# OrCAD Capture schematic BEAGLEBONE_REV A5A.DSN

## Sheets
1 P01_Title Page: title: BeagleBone Cover Page; rev: A5; note: 450-5500-001
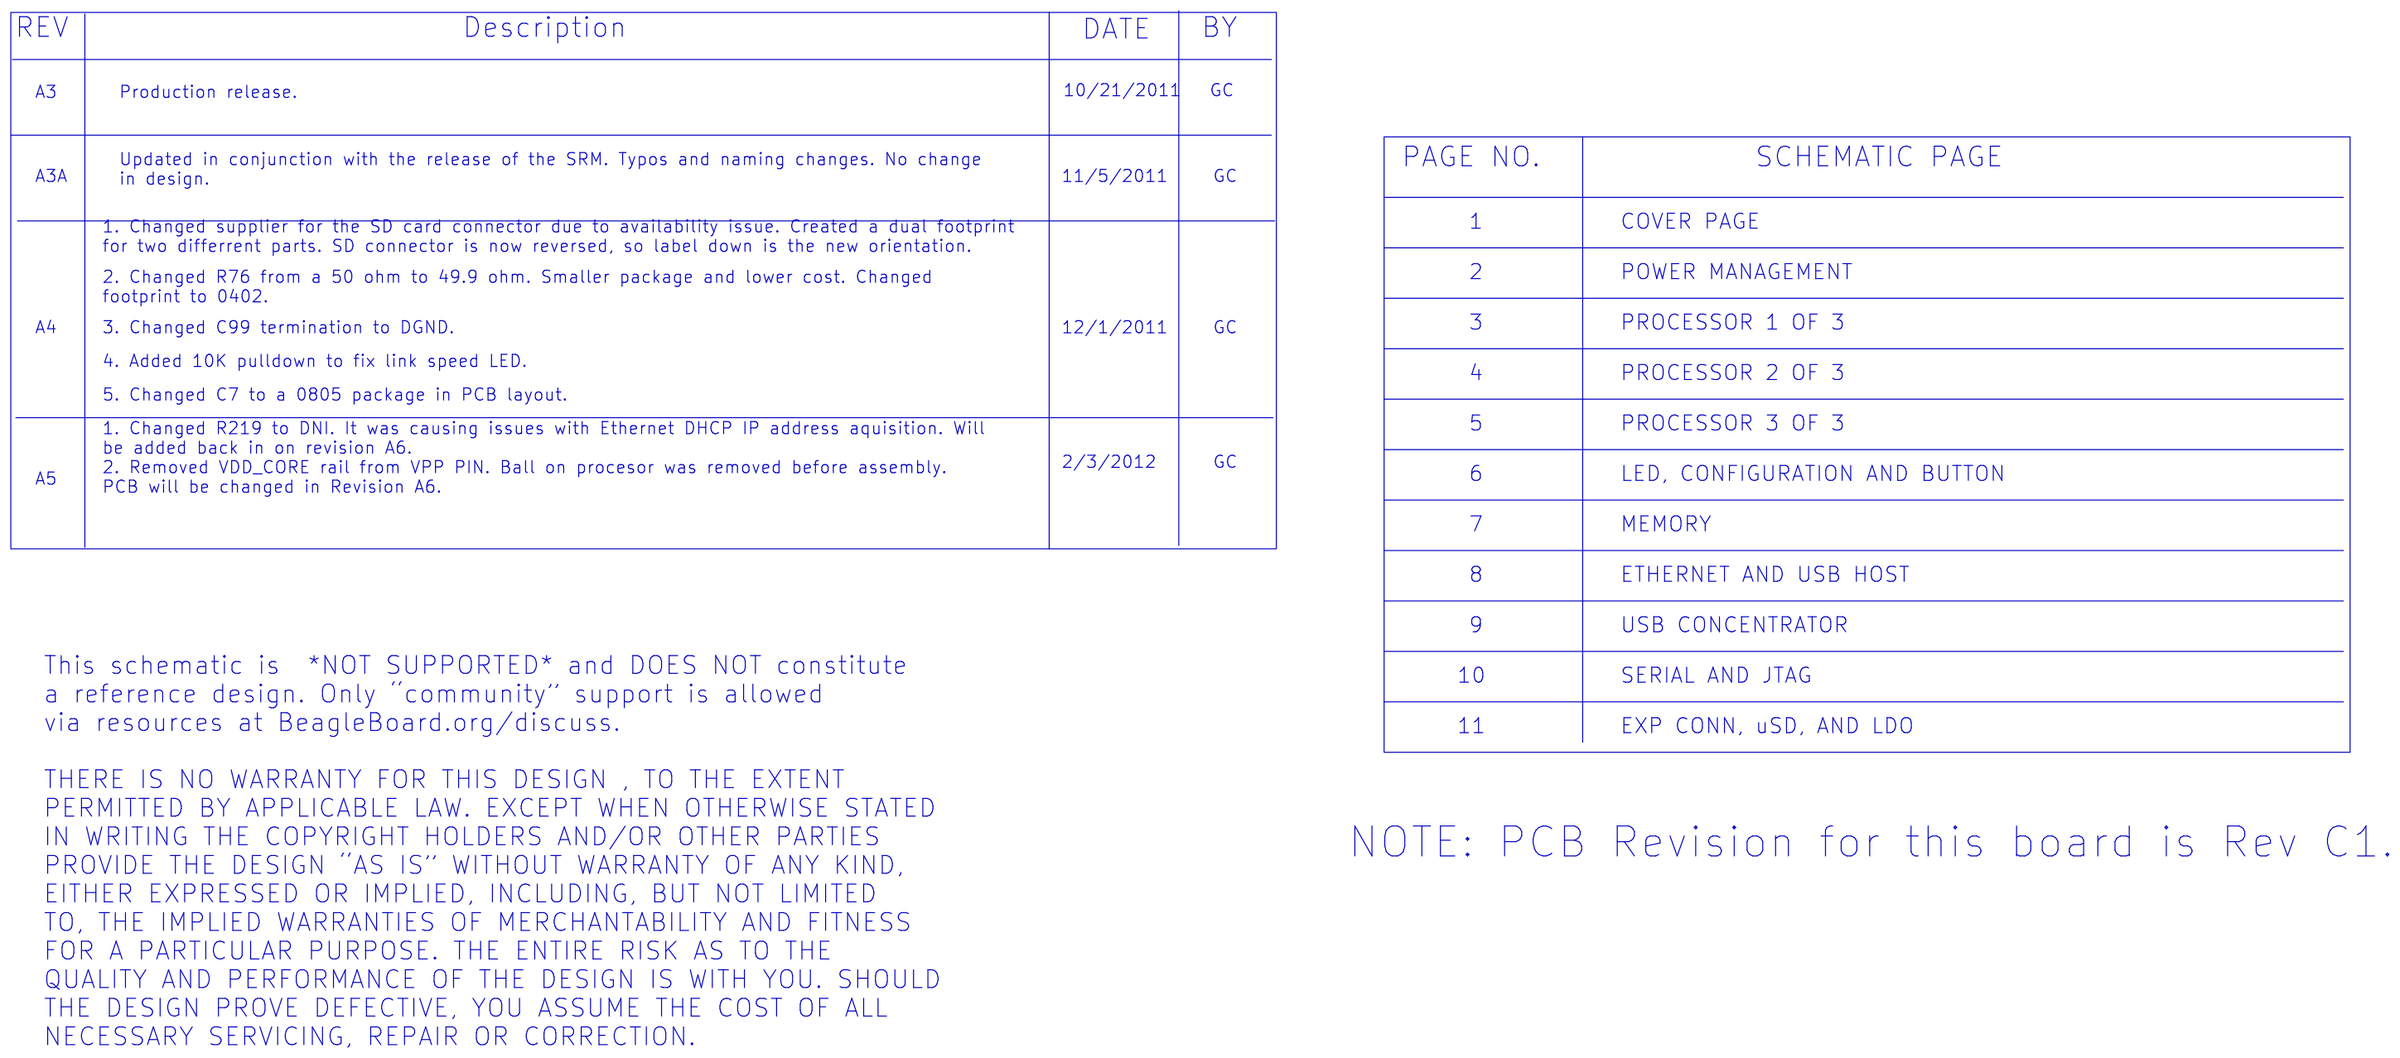
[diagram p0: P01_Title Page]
2 P02_Power Management: size B; title: BeagleBone Power Management
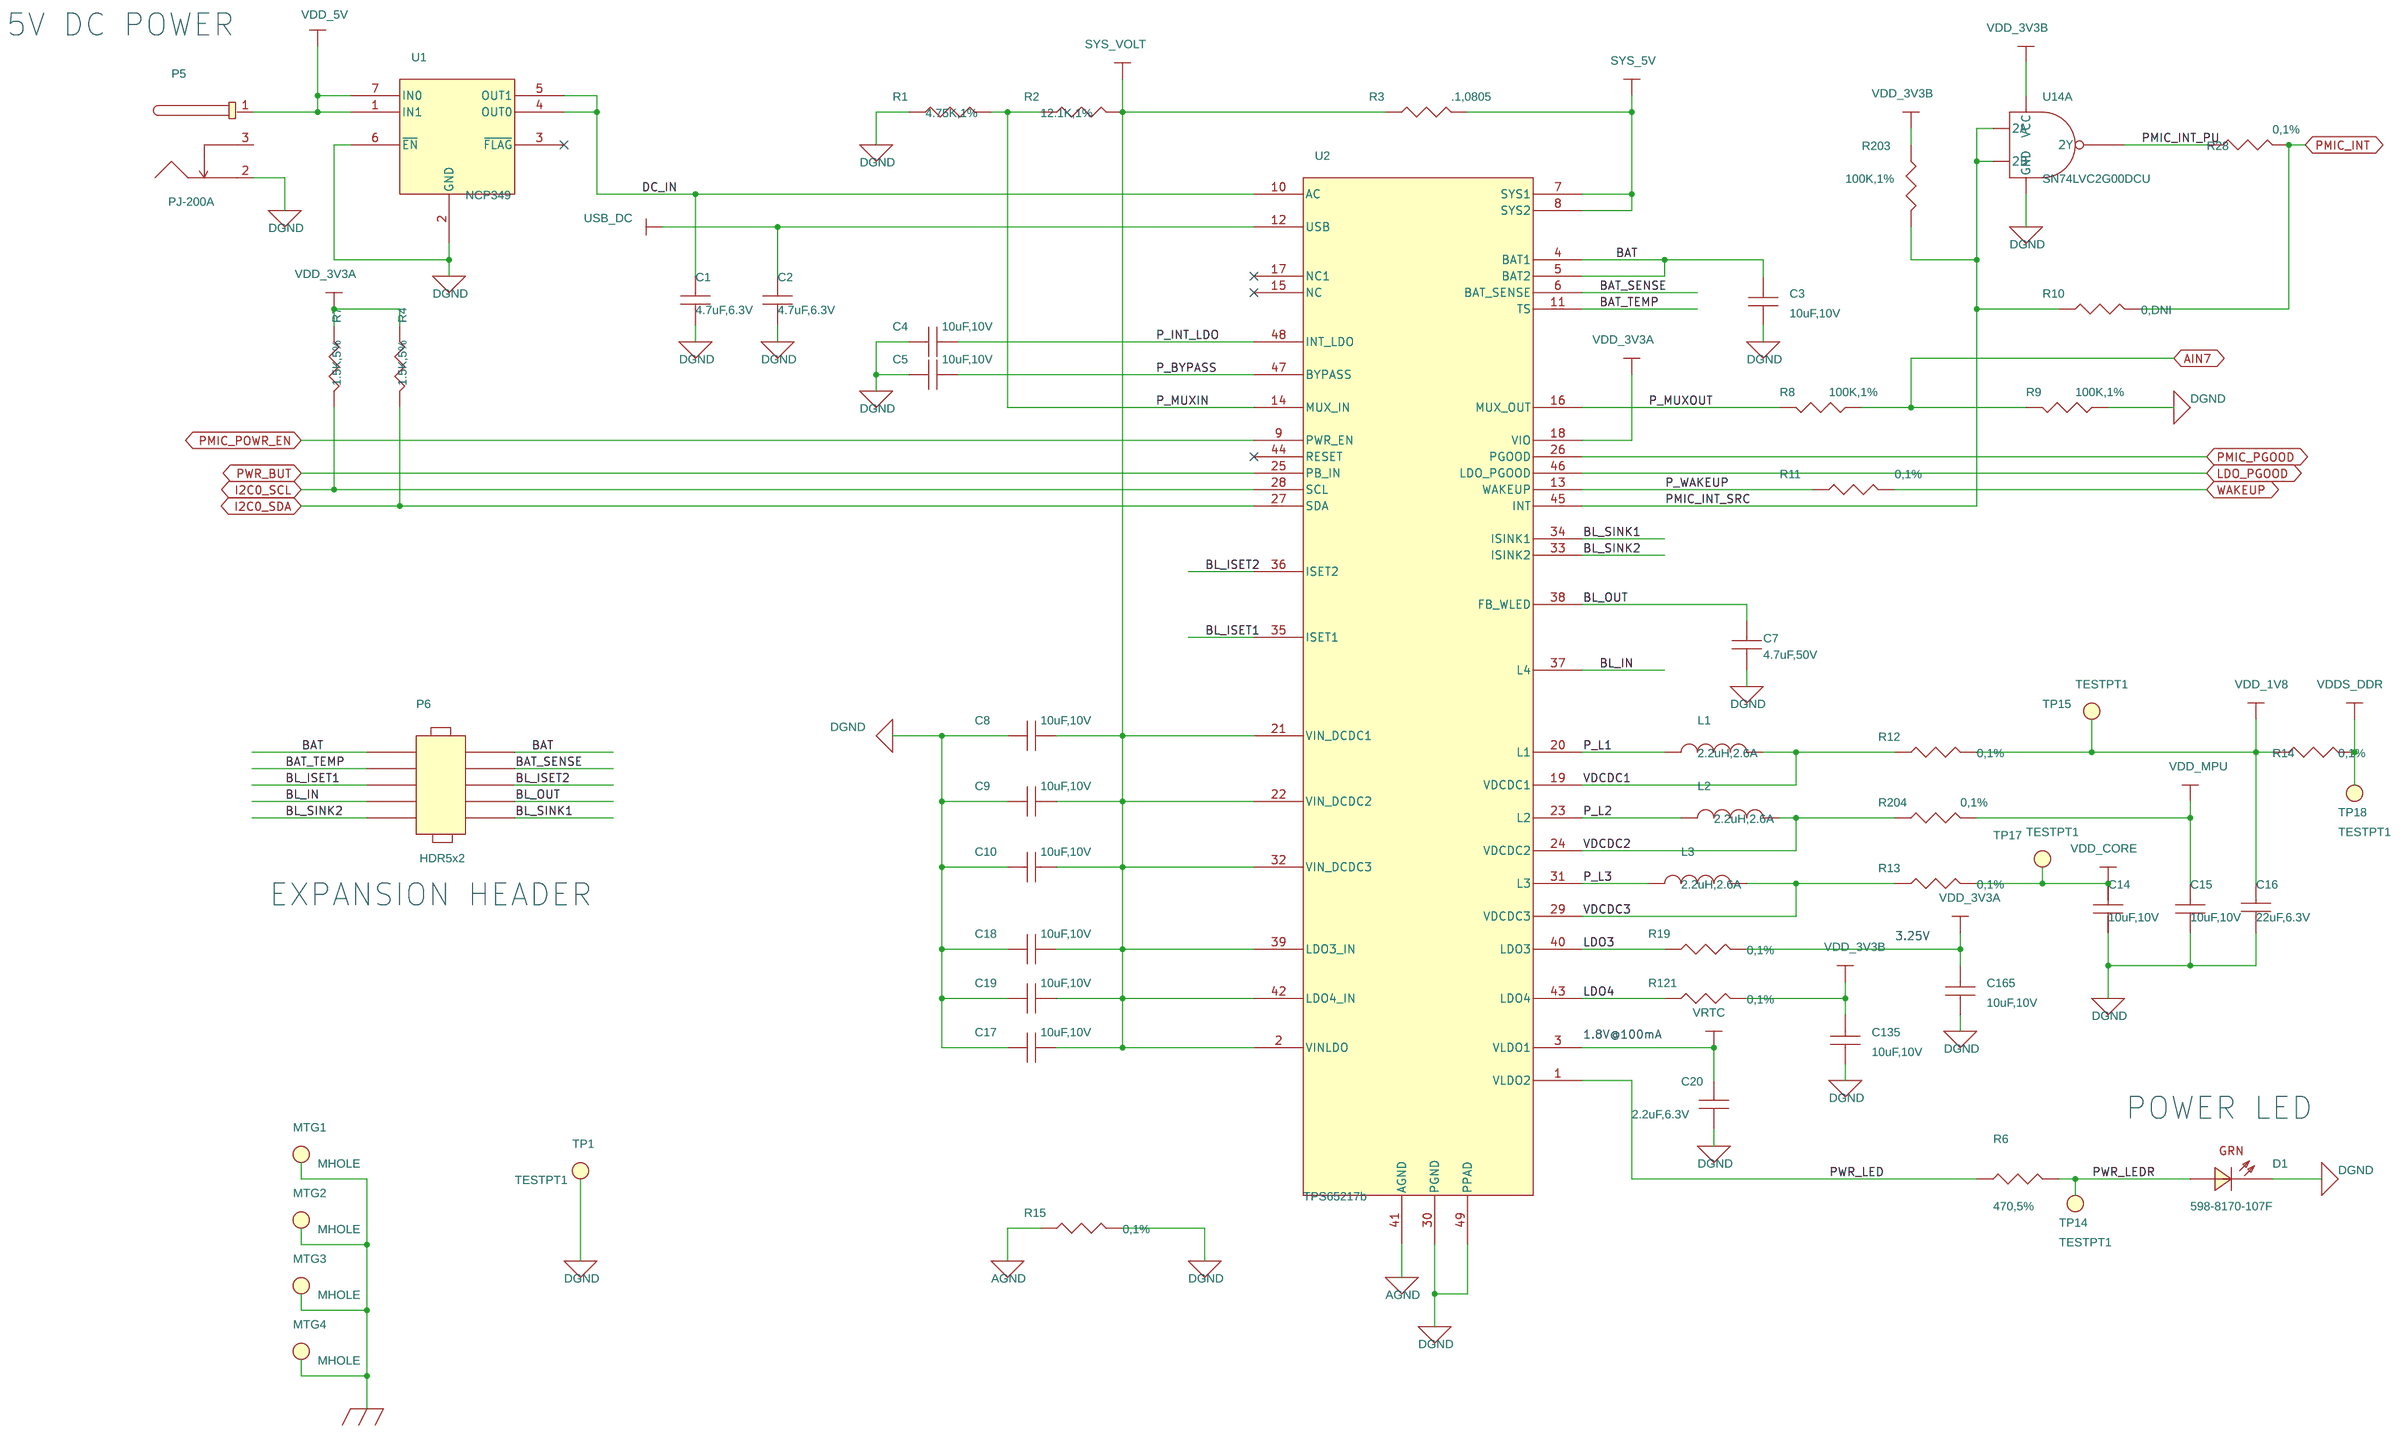
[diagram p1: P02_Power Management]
3 P03_AM335x Sheet 1 of 3: size C; title: BeagleBone Processor 1 of 3
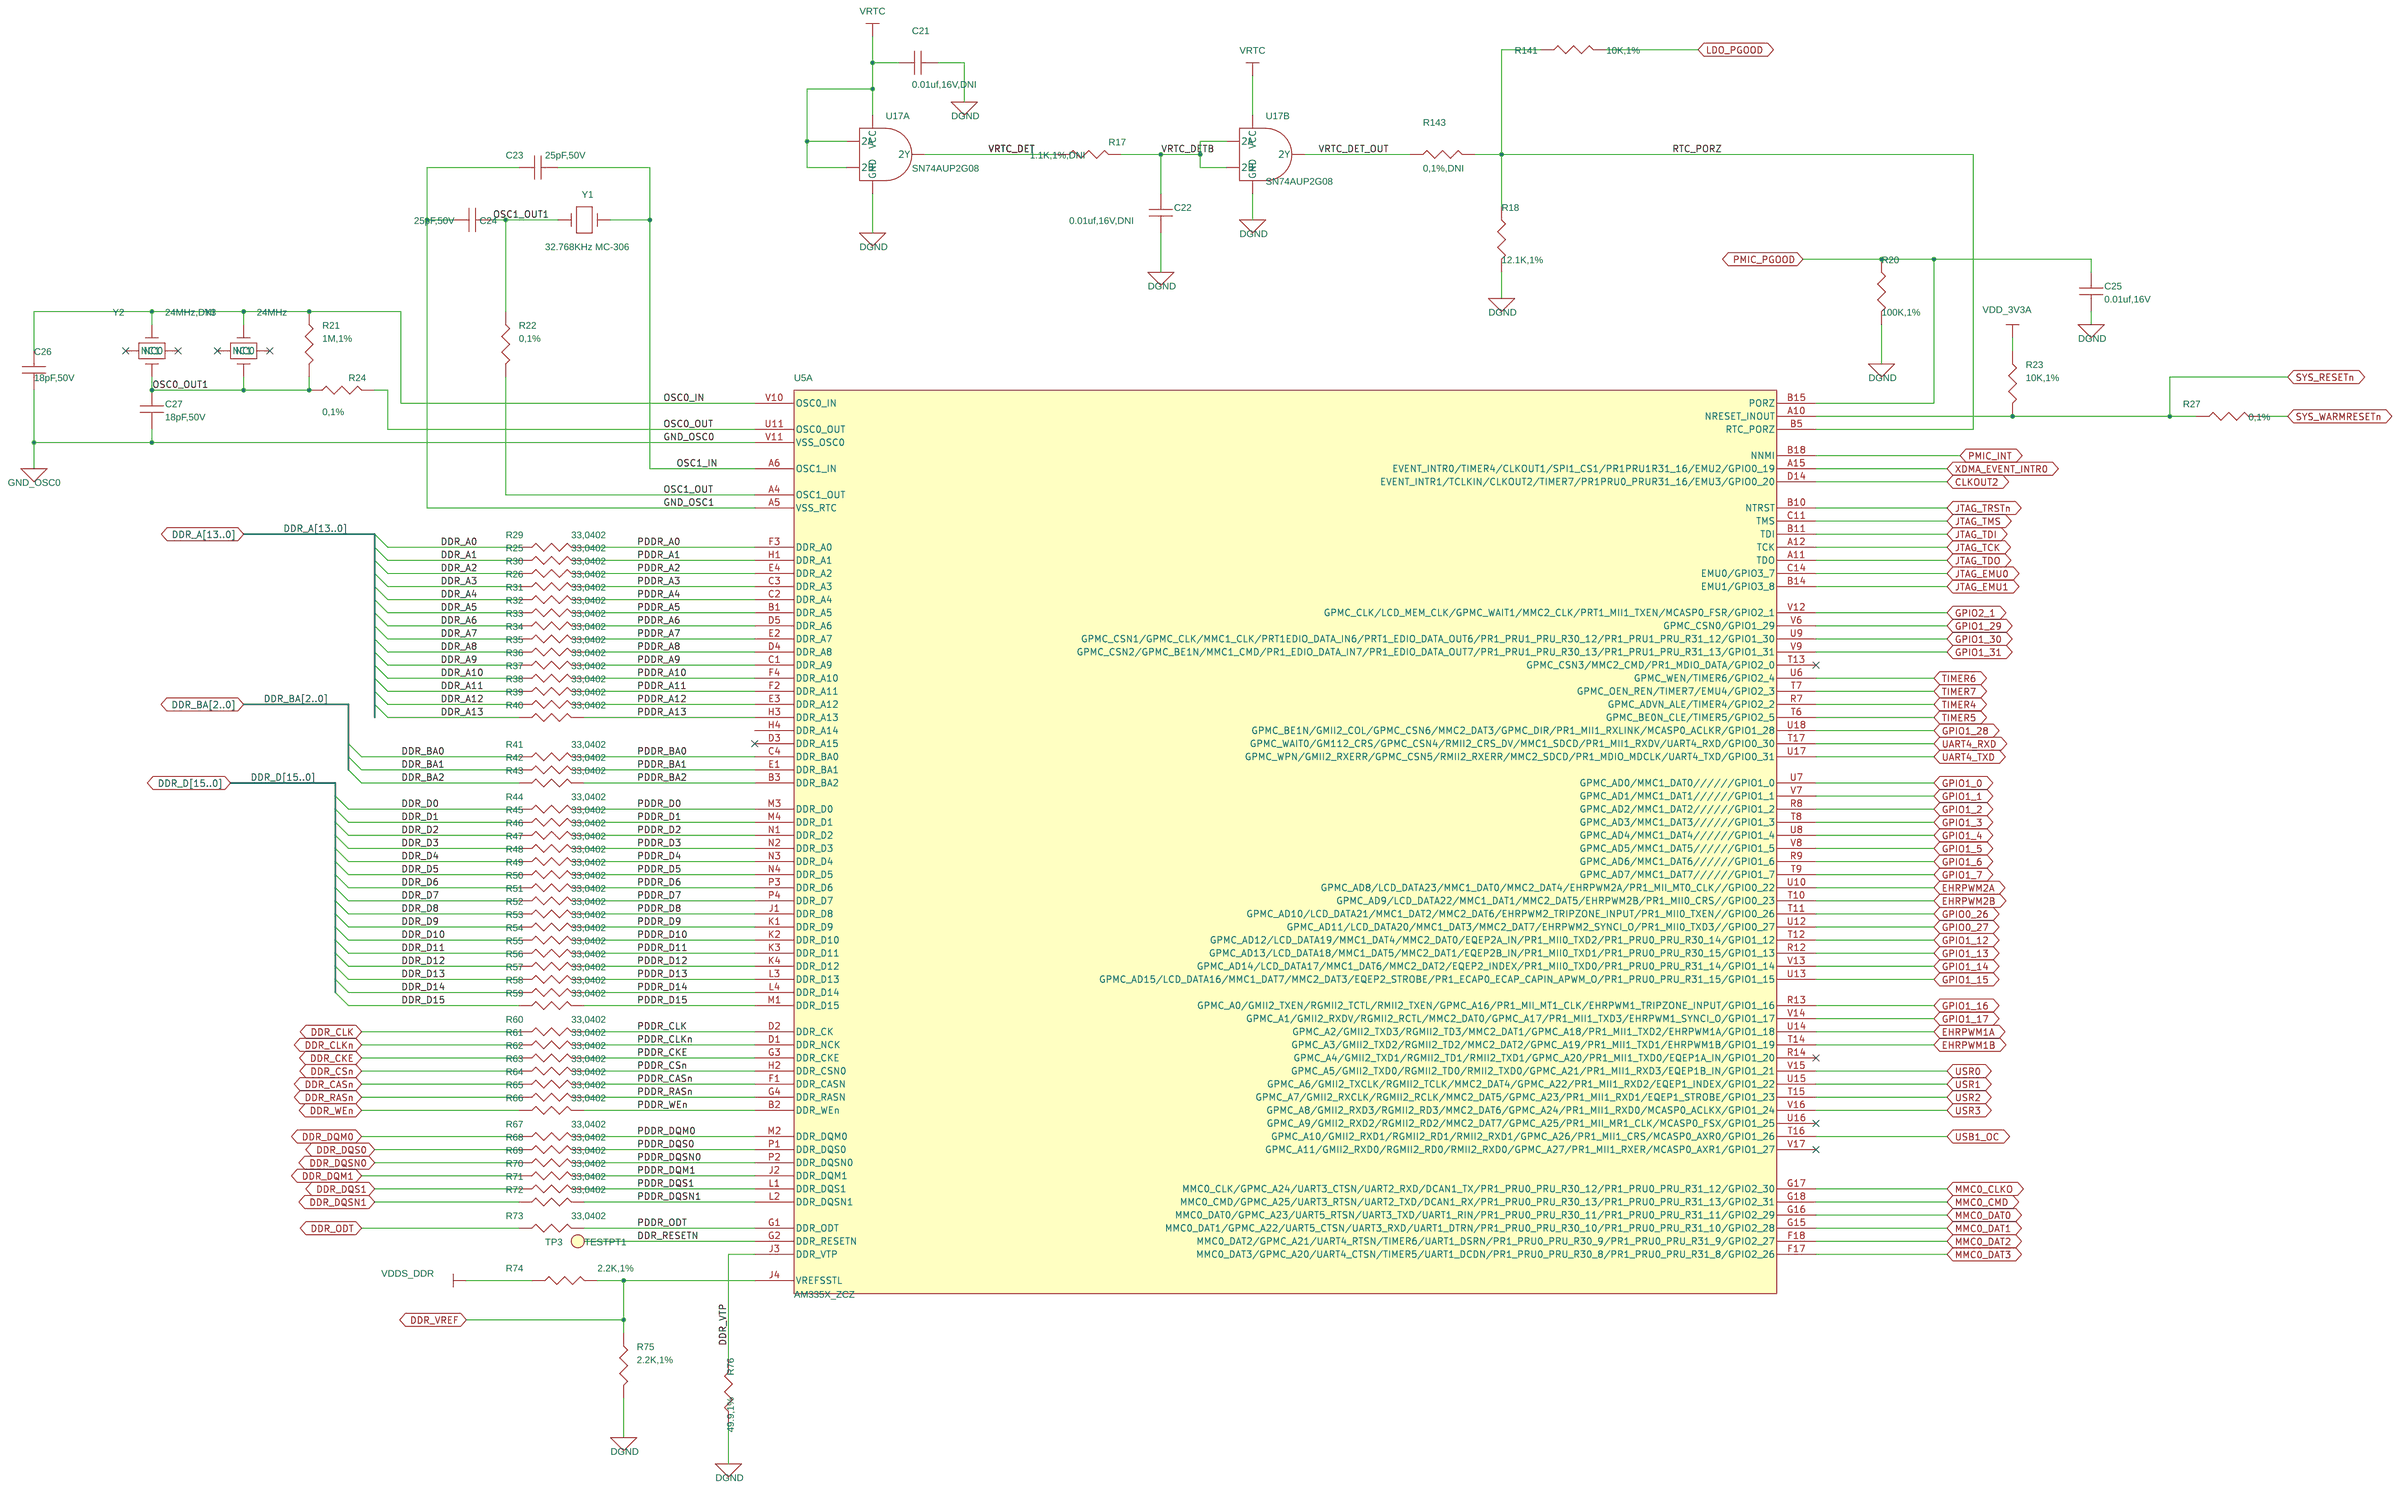
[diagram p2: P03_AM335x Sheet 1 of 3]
4 P04_AM335x Sheet 2 of 3: size C; title: BeagleBone Processor 2 of 3
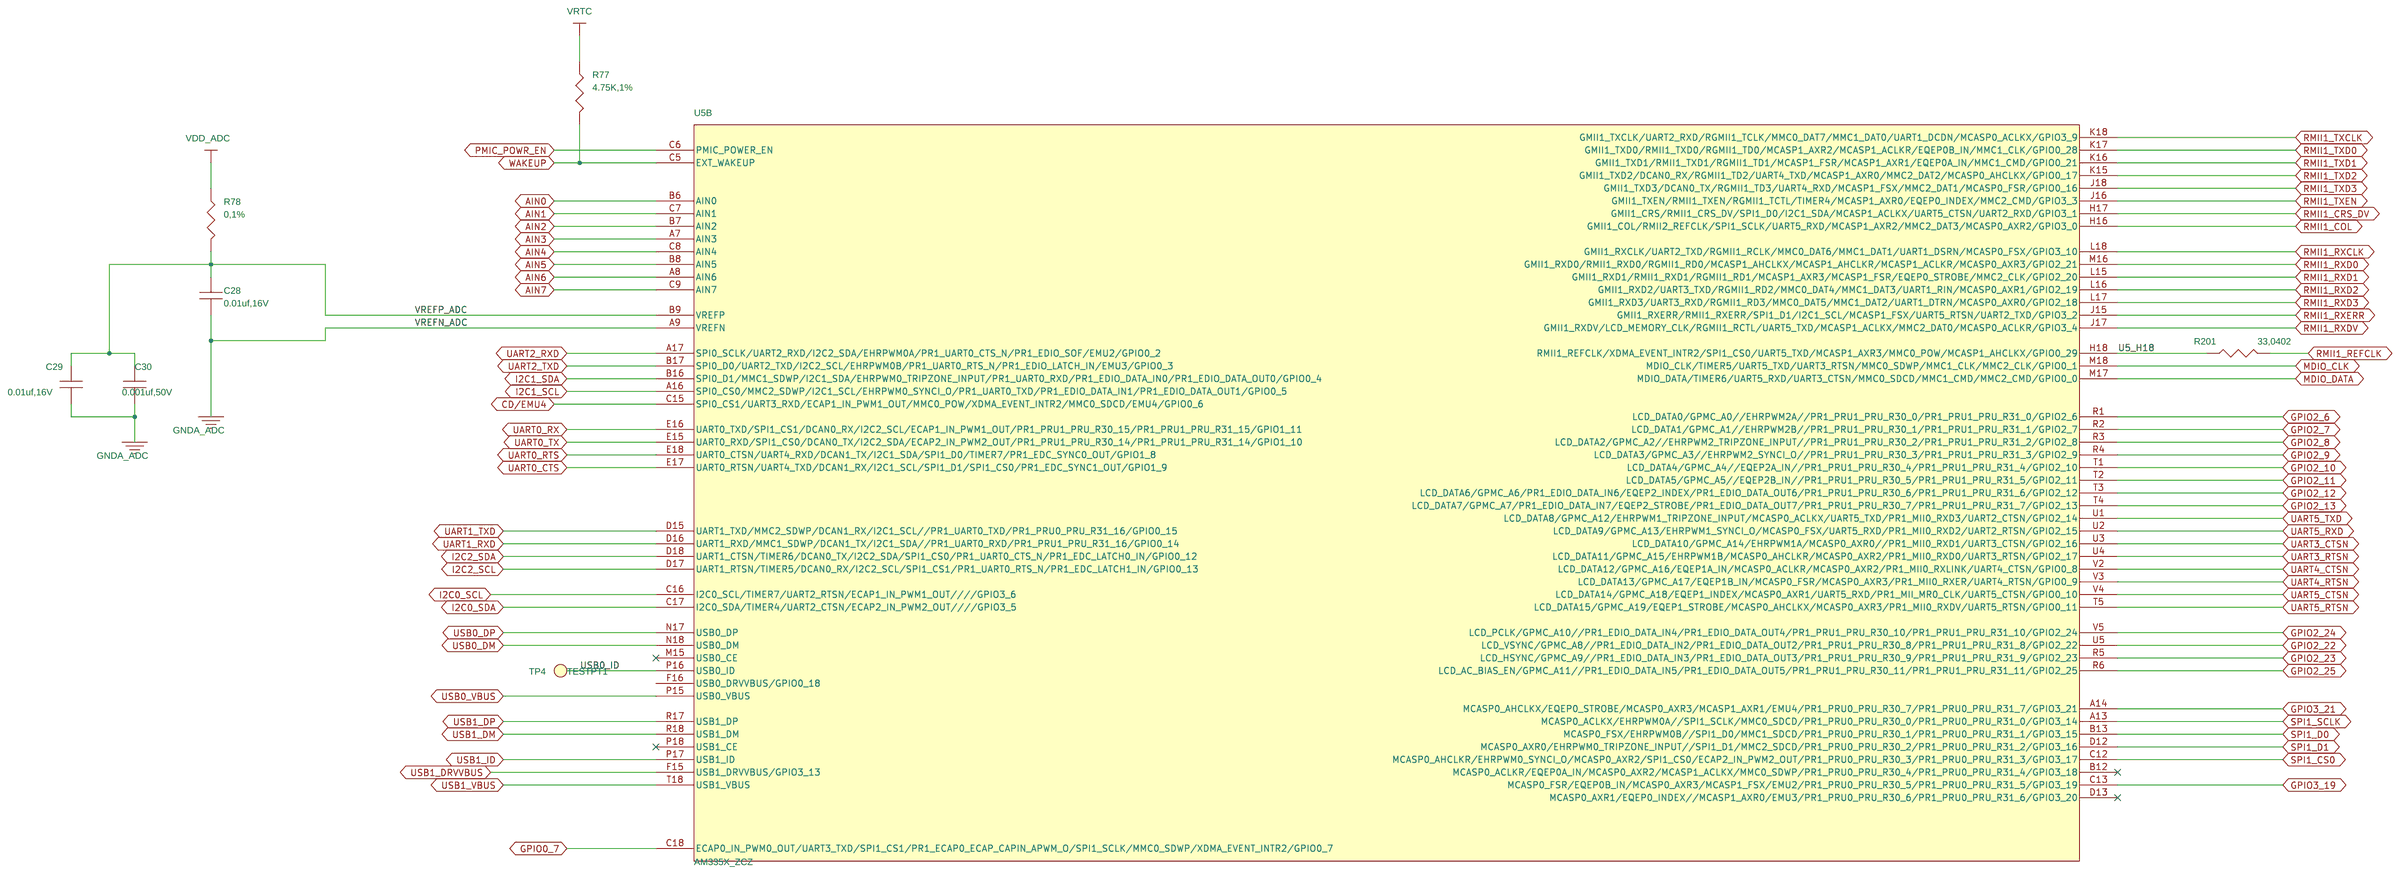
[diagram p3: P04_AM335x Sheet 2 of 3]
5 P05_AM335x Page 3 of 3: size C; title: BeagleBone Processr 3 of 3
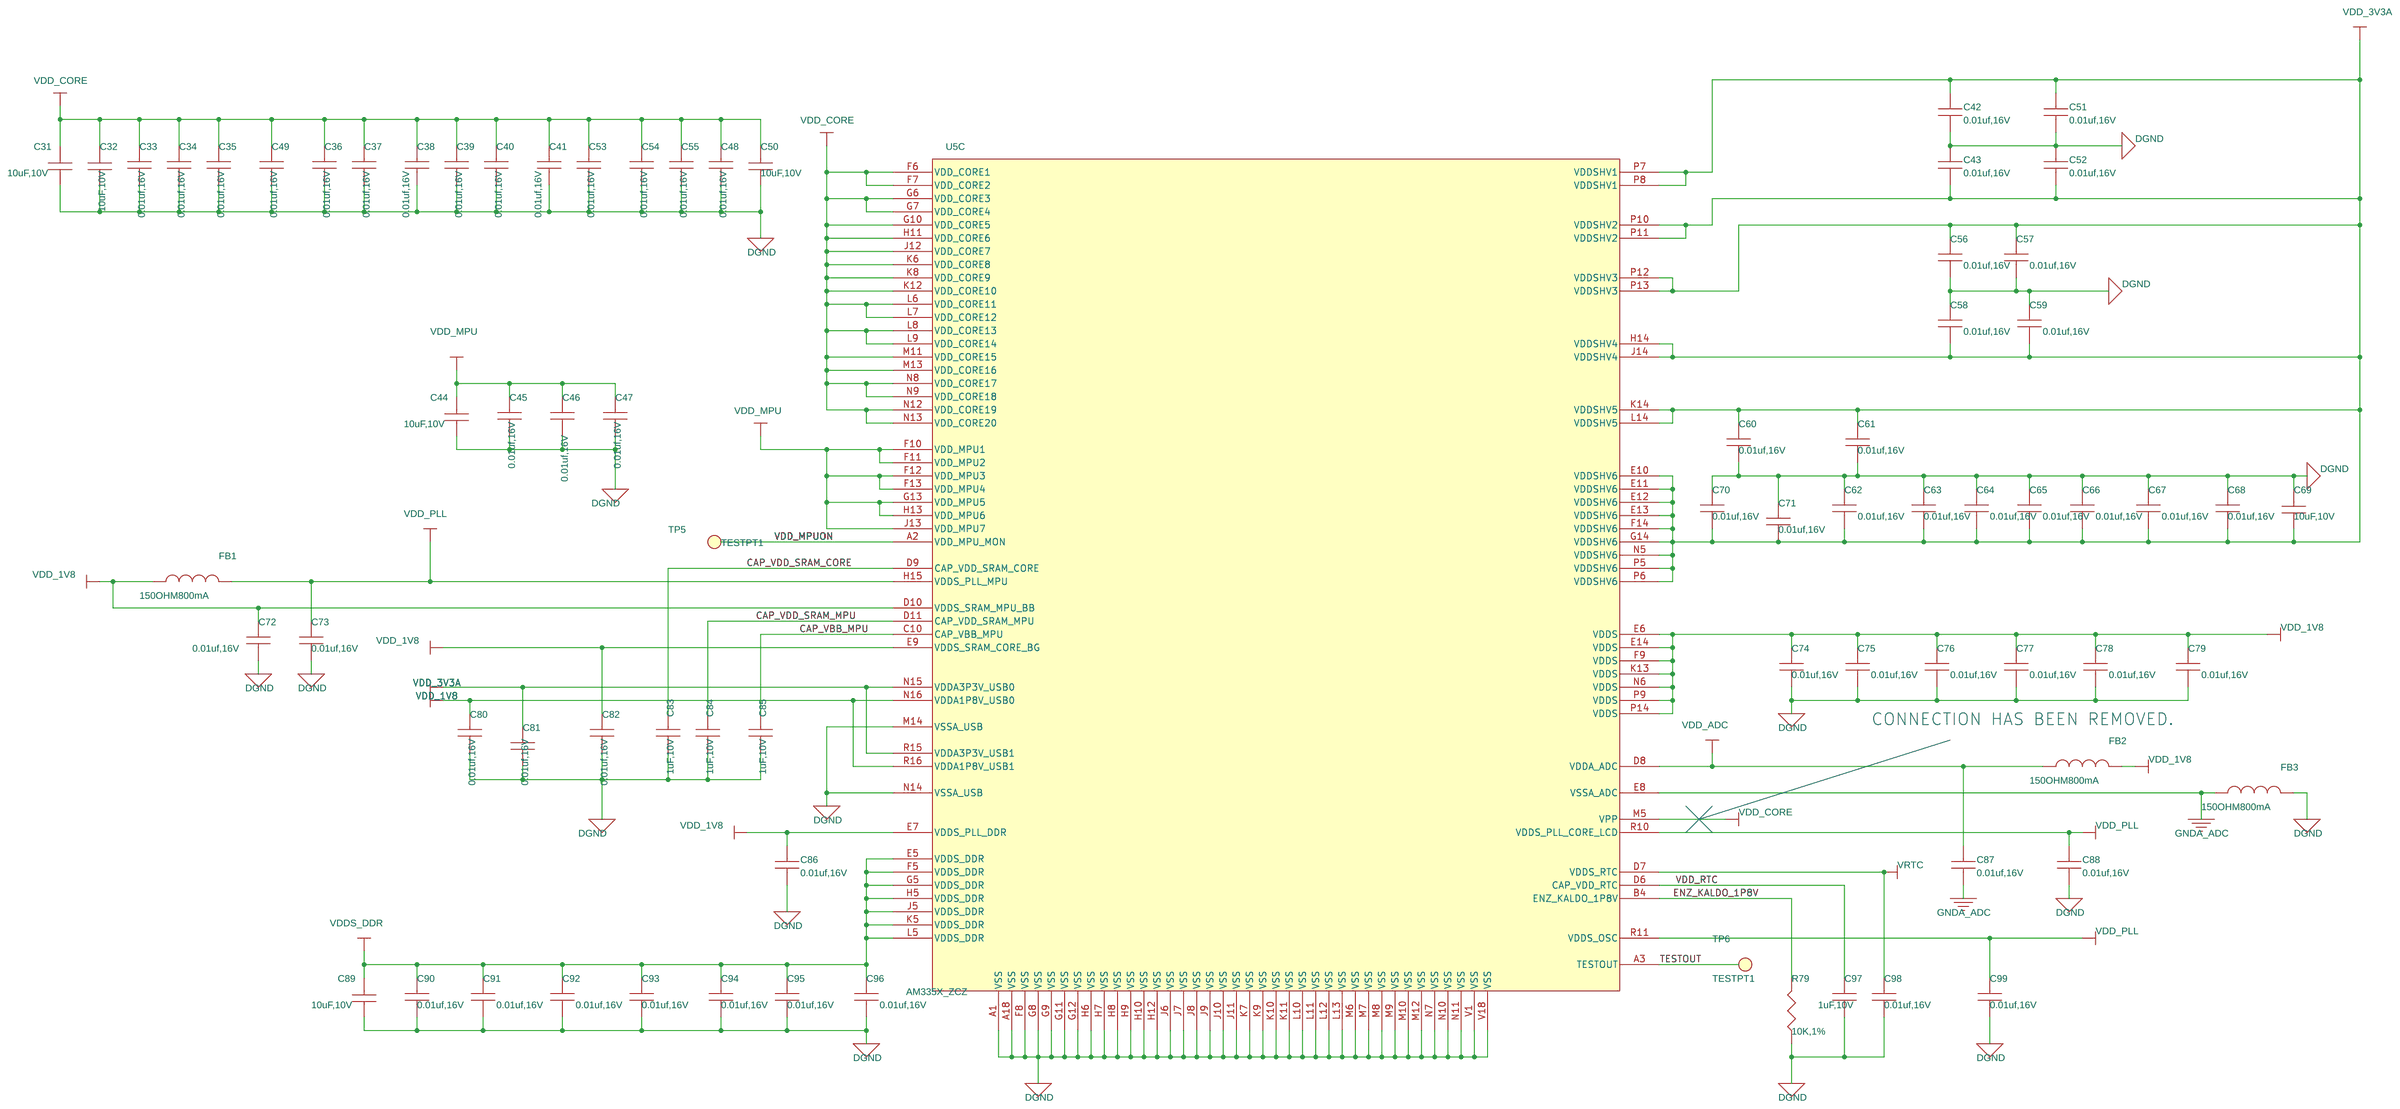
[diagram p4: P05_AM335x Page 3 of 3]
6 P06_LED, Config, & Reset: size B; title: BeagleBone LED, Configuration and Reset
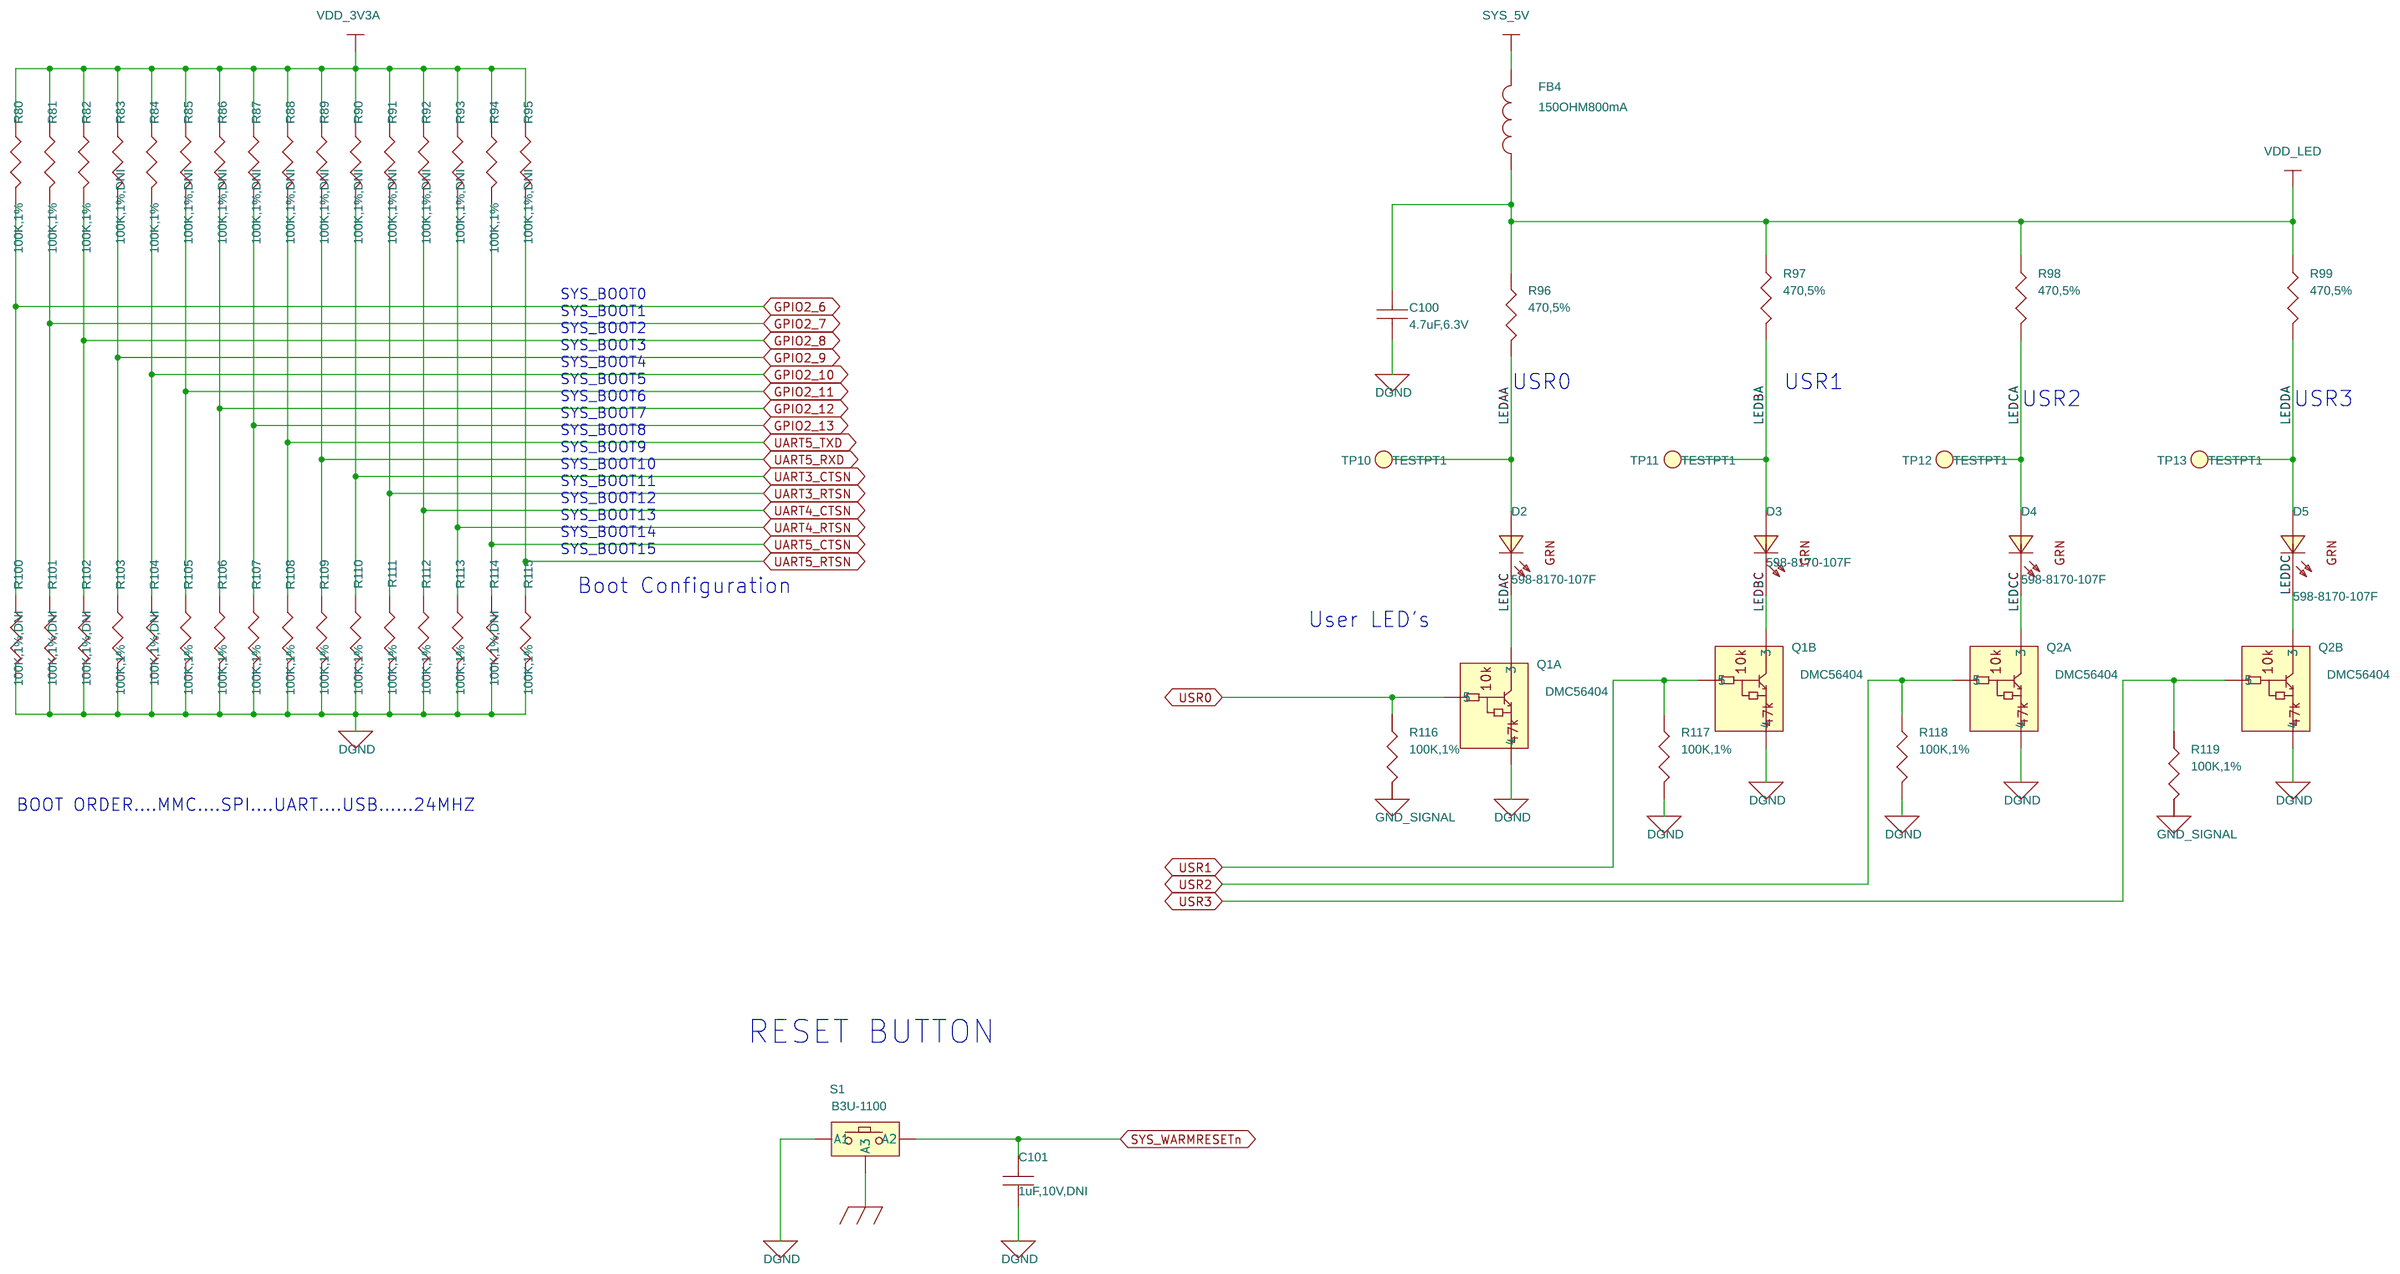
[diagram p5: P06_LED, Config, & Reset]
7 P07_Memory: size B; title: BeagleBone DDR2 Memory
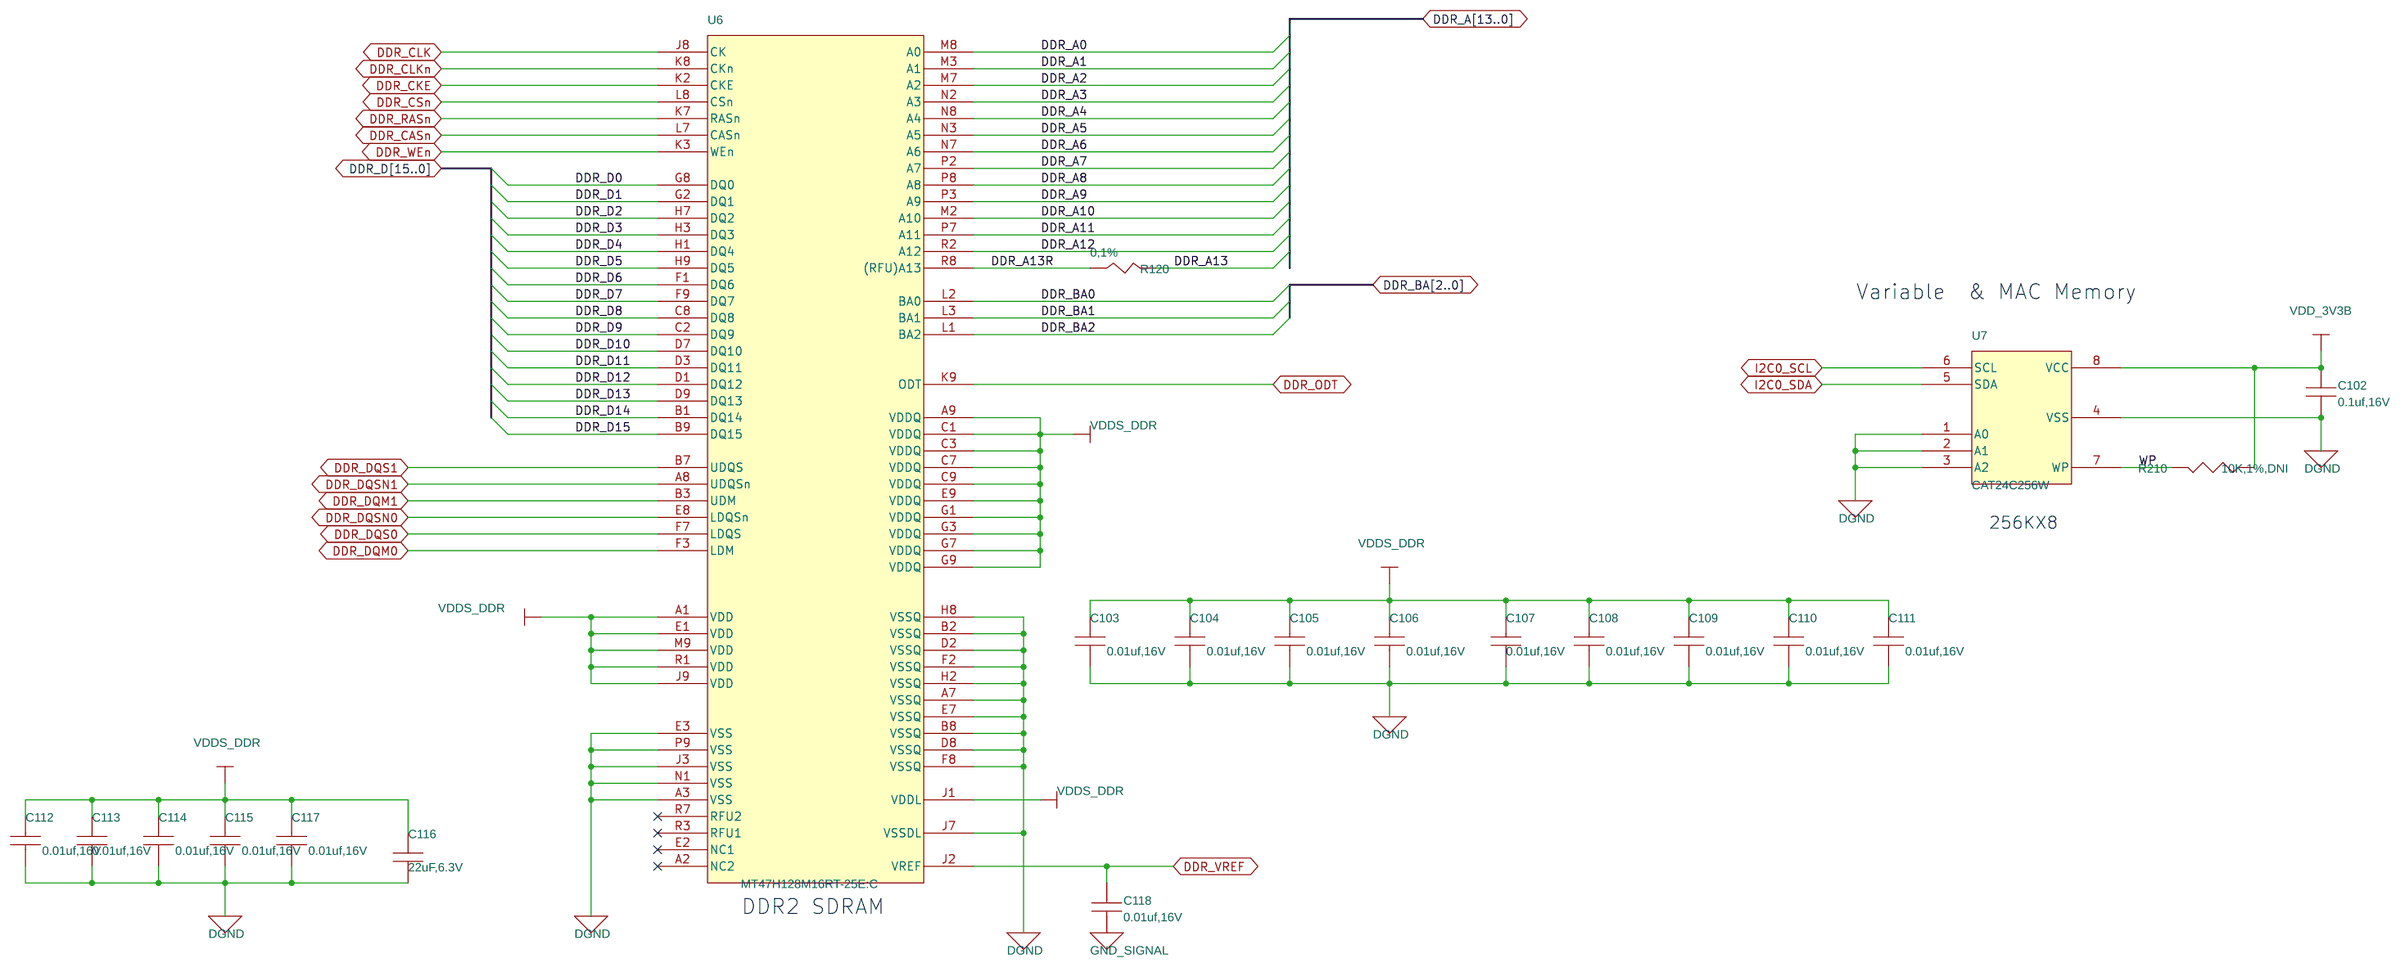
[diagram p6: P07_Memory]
8 P08_Ethernet and USB Host: size C; title: BeagleBone Ethernet and USB Host
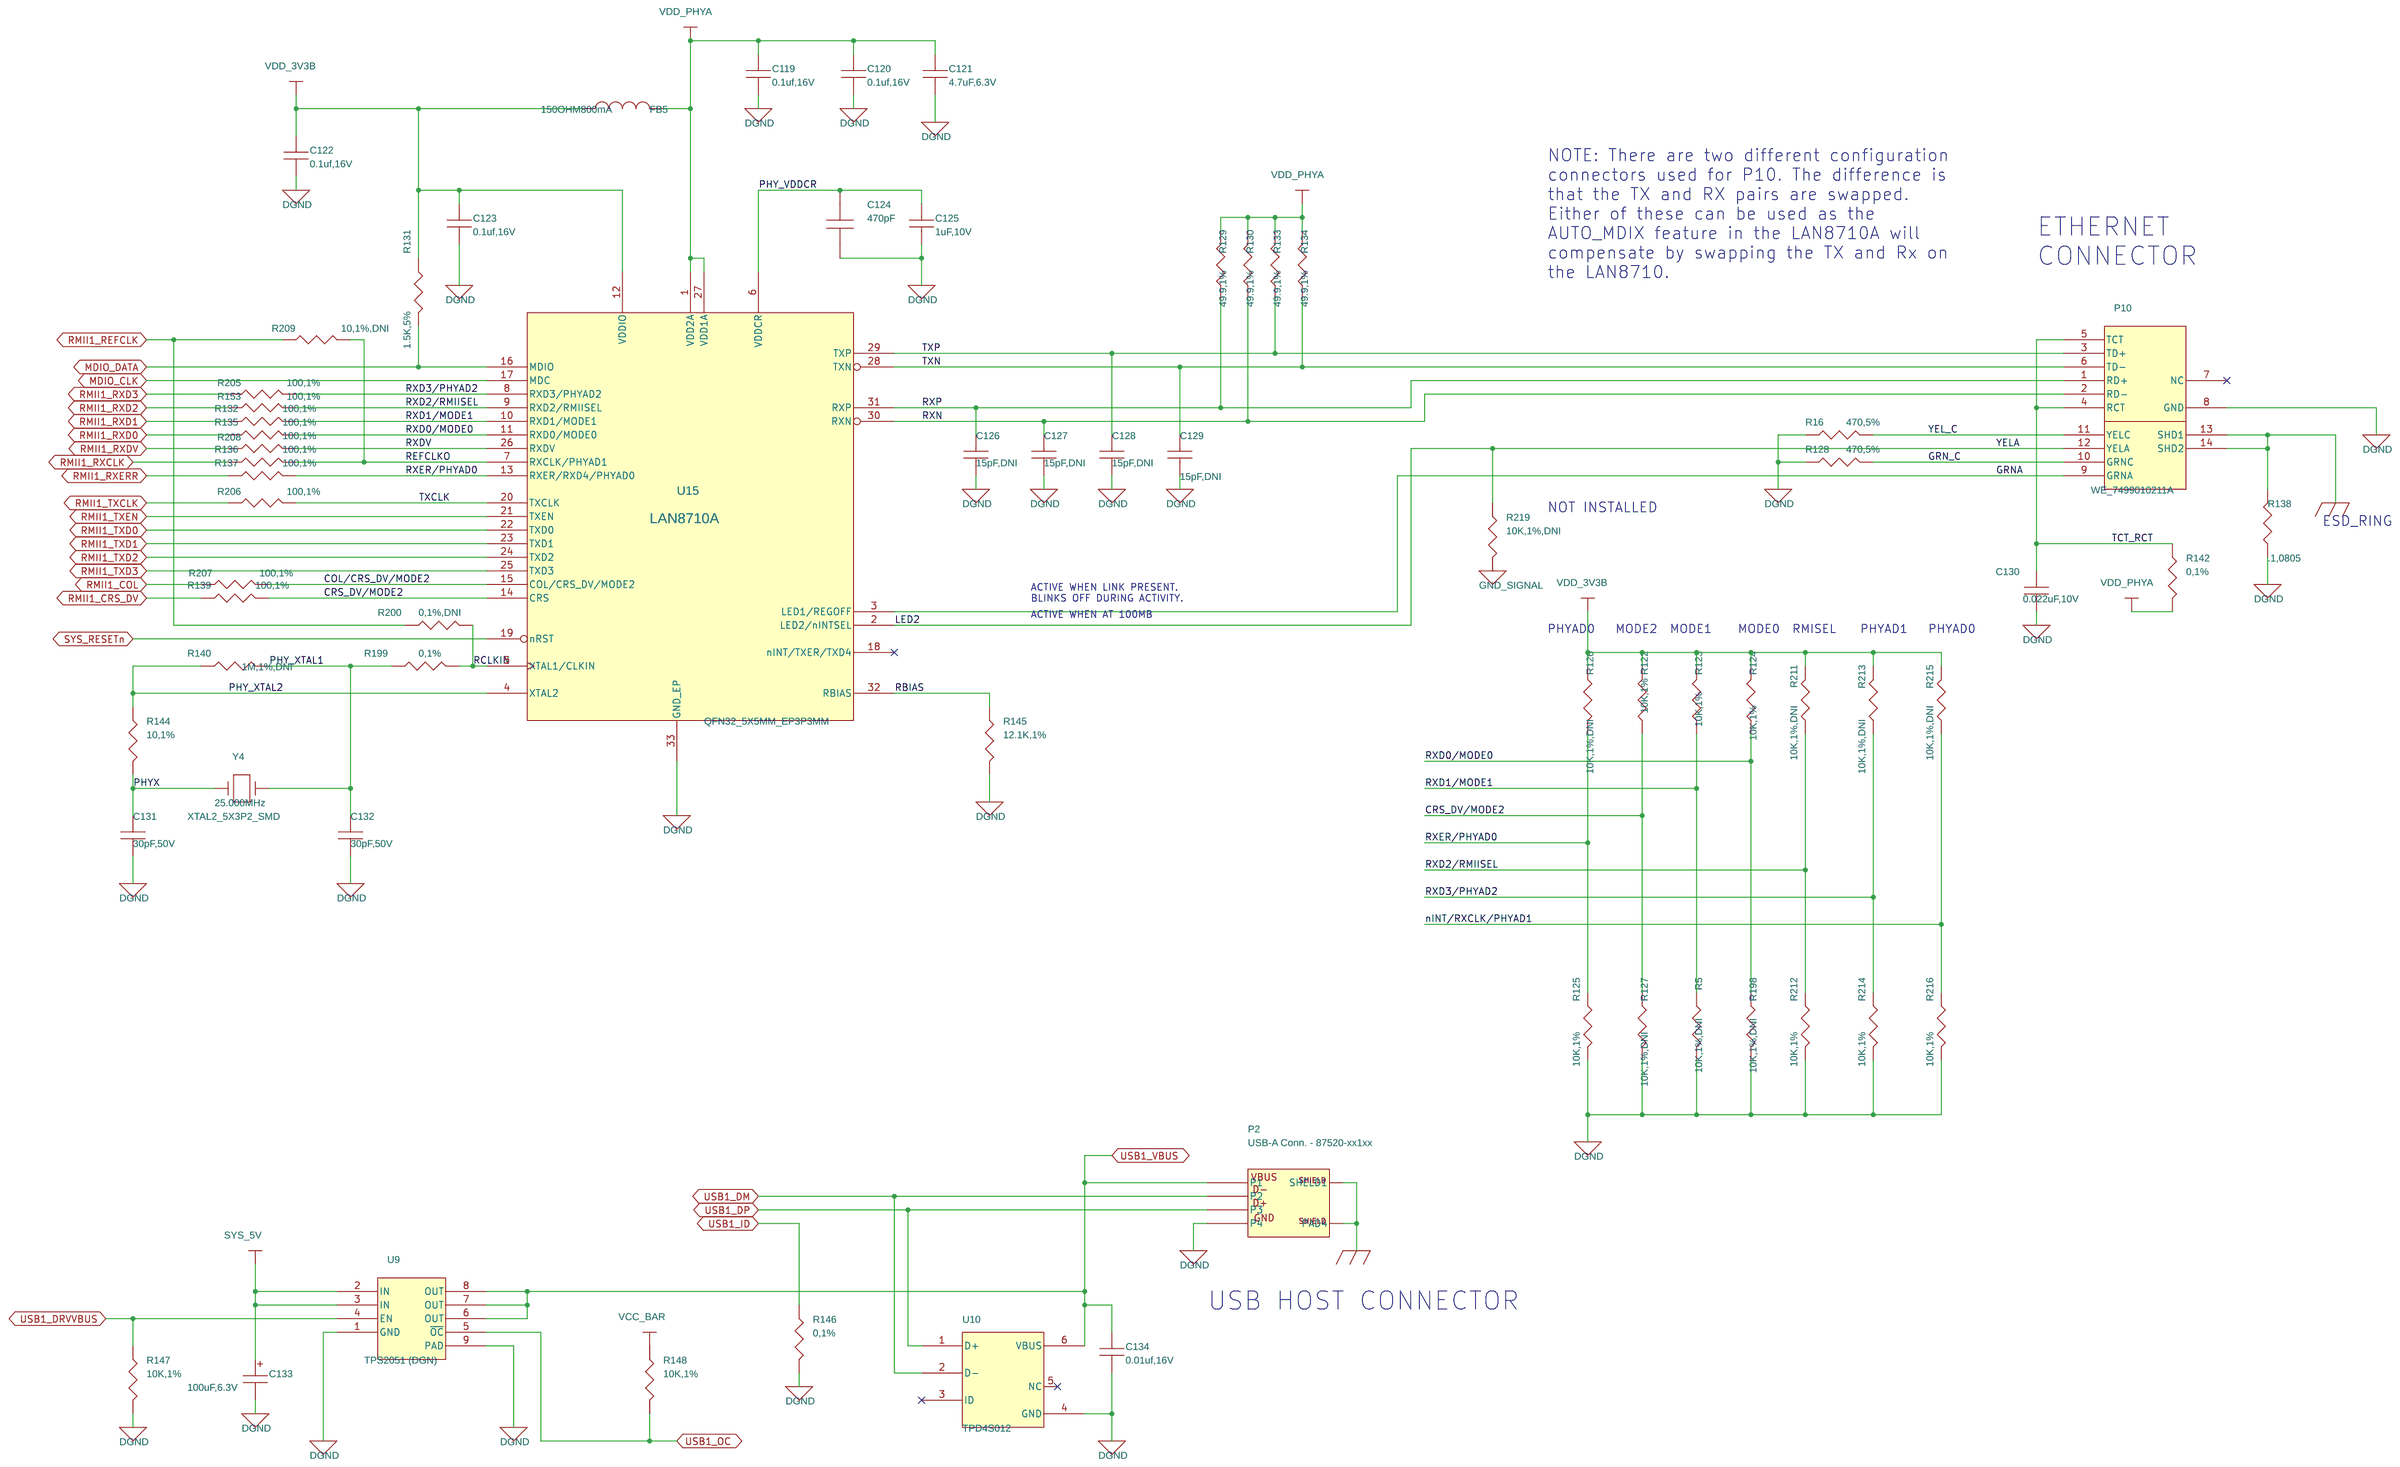
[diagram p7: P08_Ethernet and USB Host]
9 P09_USB Port Concentrator: size B; title: BeagleBone USB Concentrator
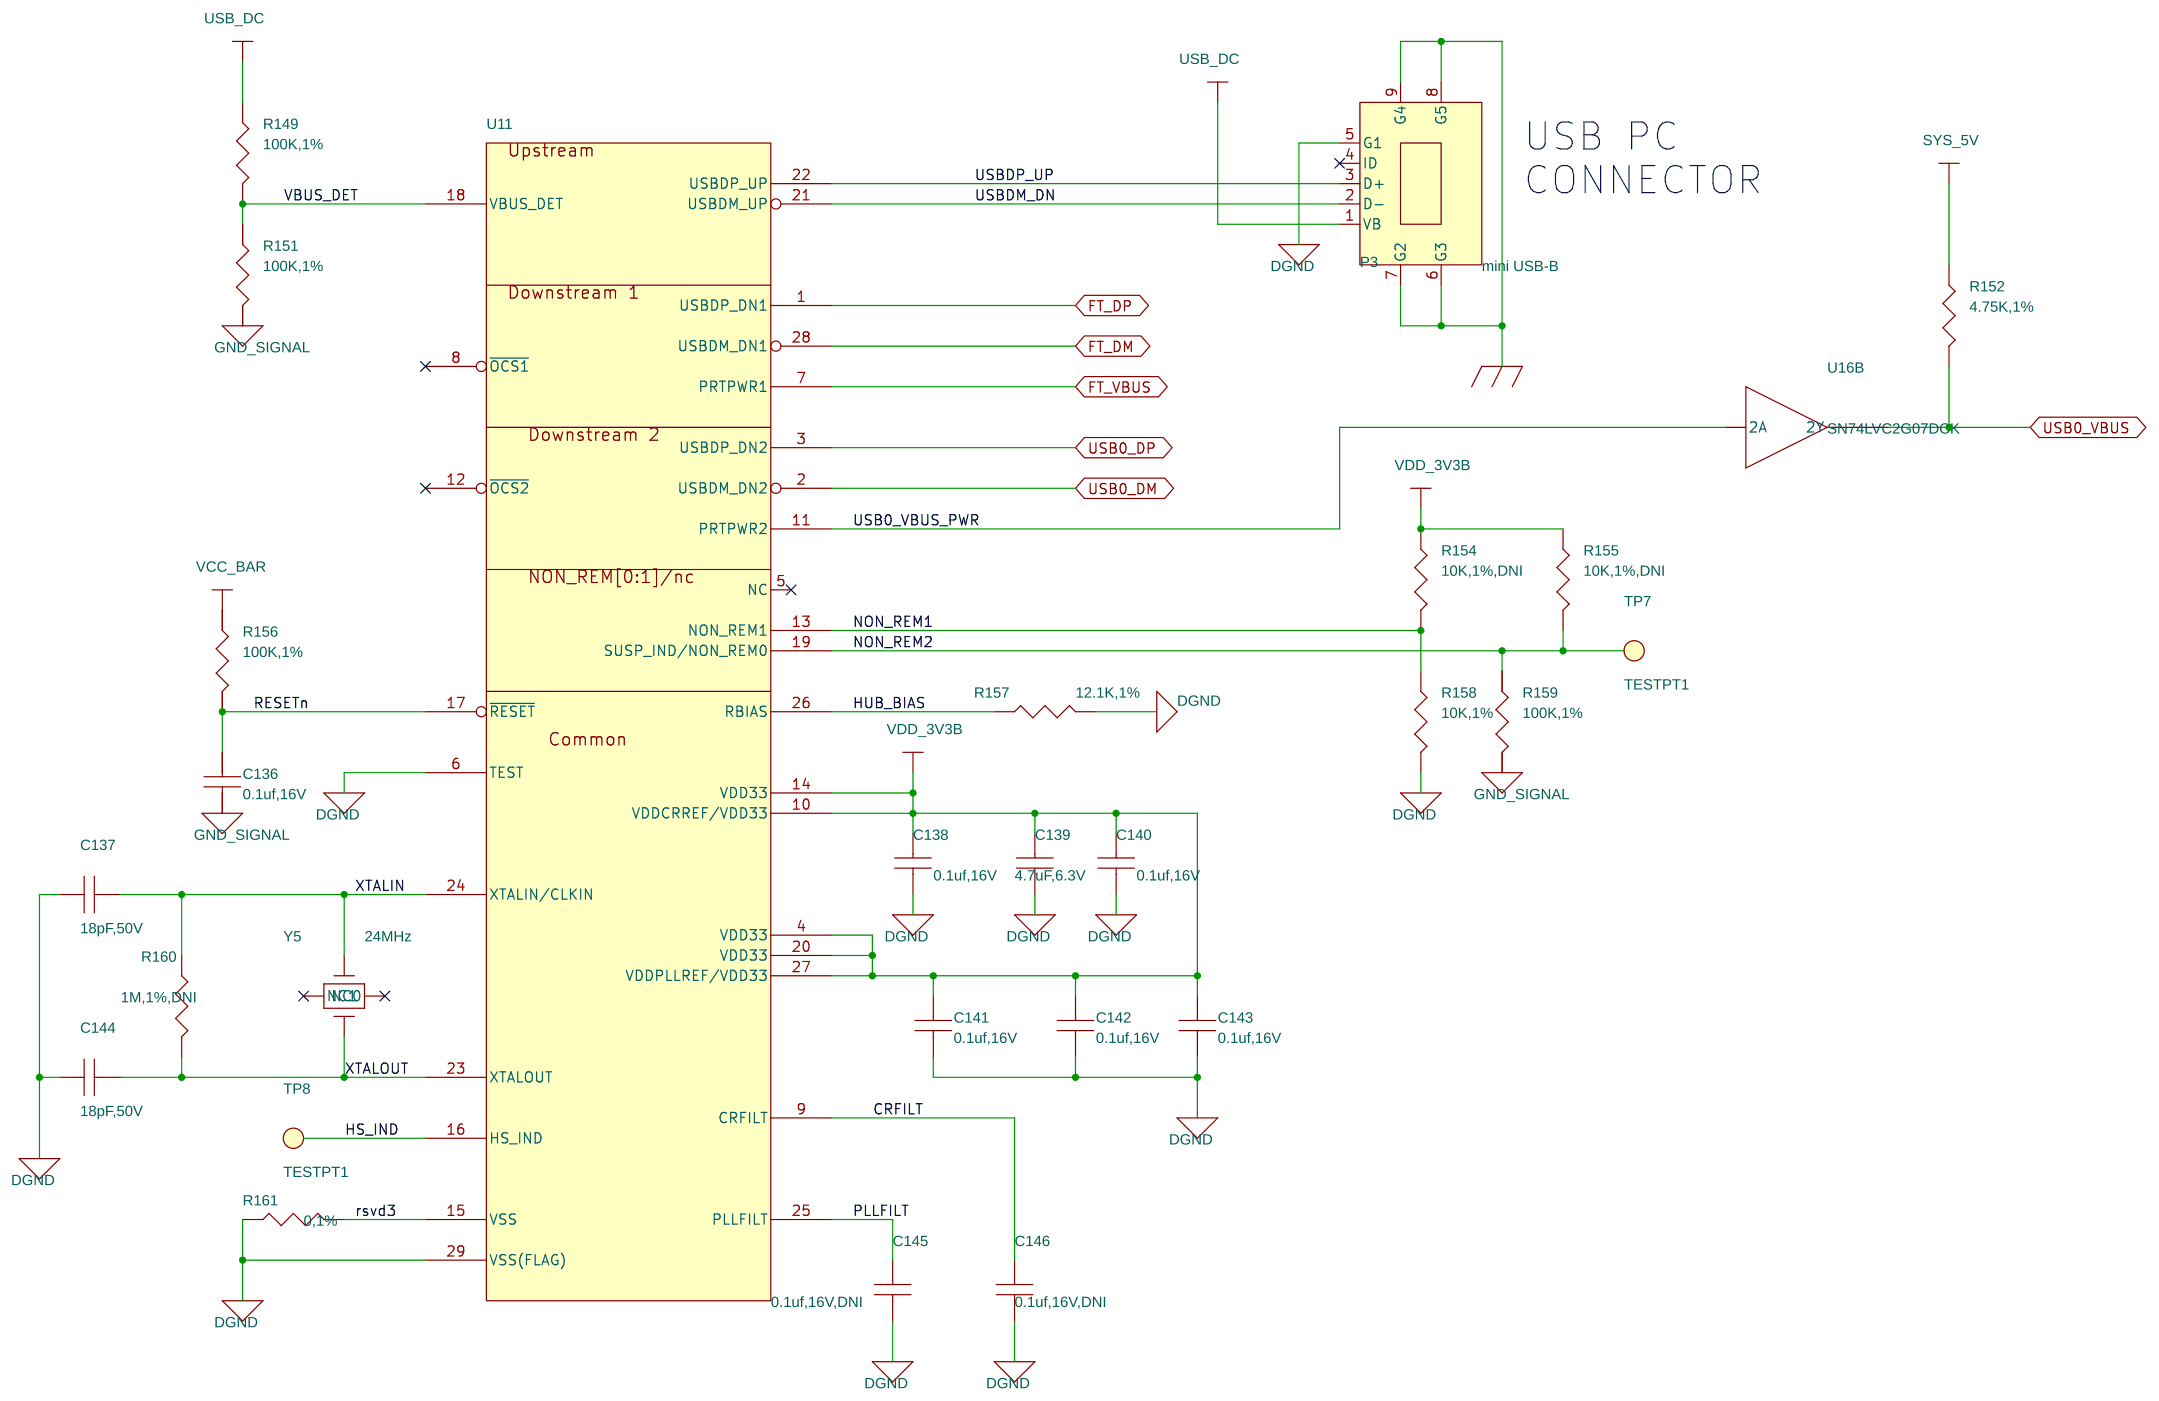
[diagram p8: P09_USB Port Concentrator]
10 P10_Serial and JTAG: size B; title: BeagleBone Serial and JTAG
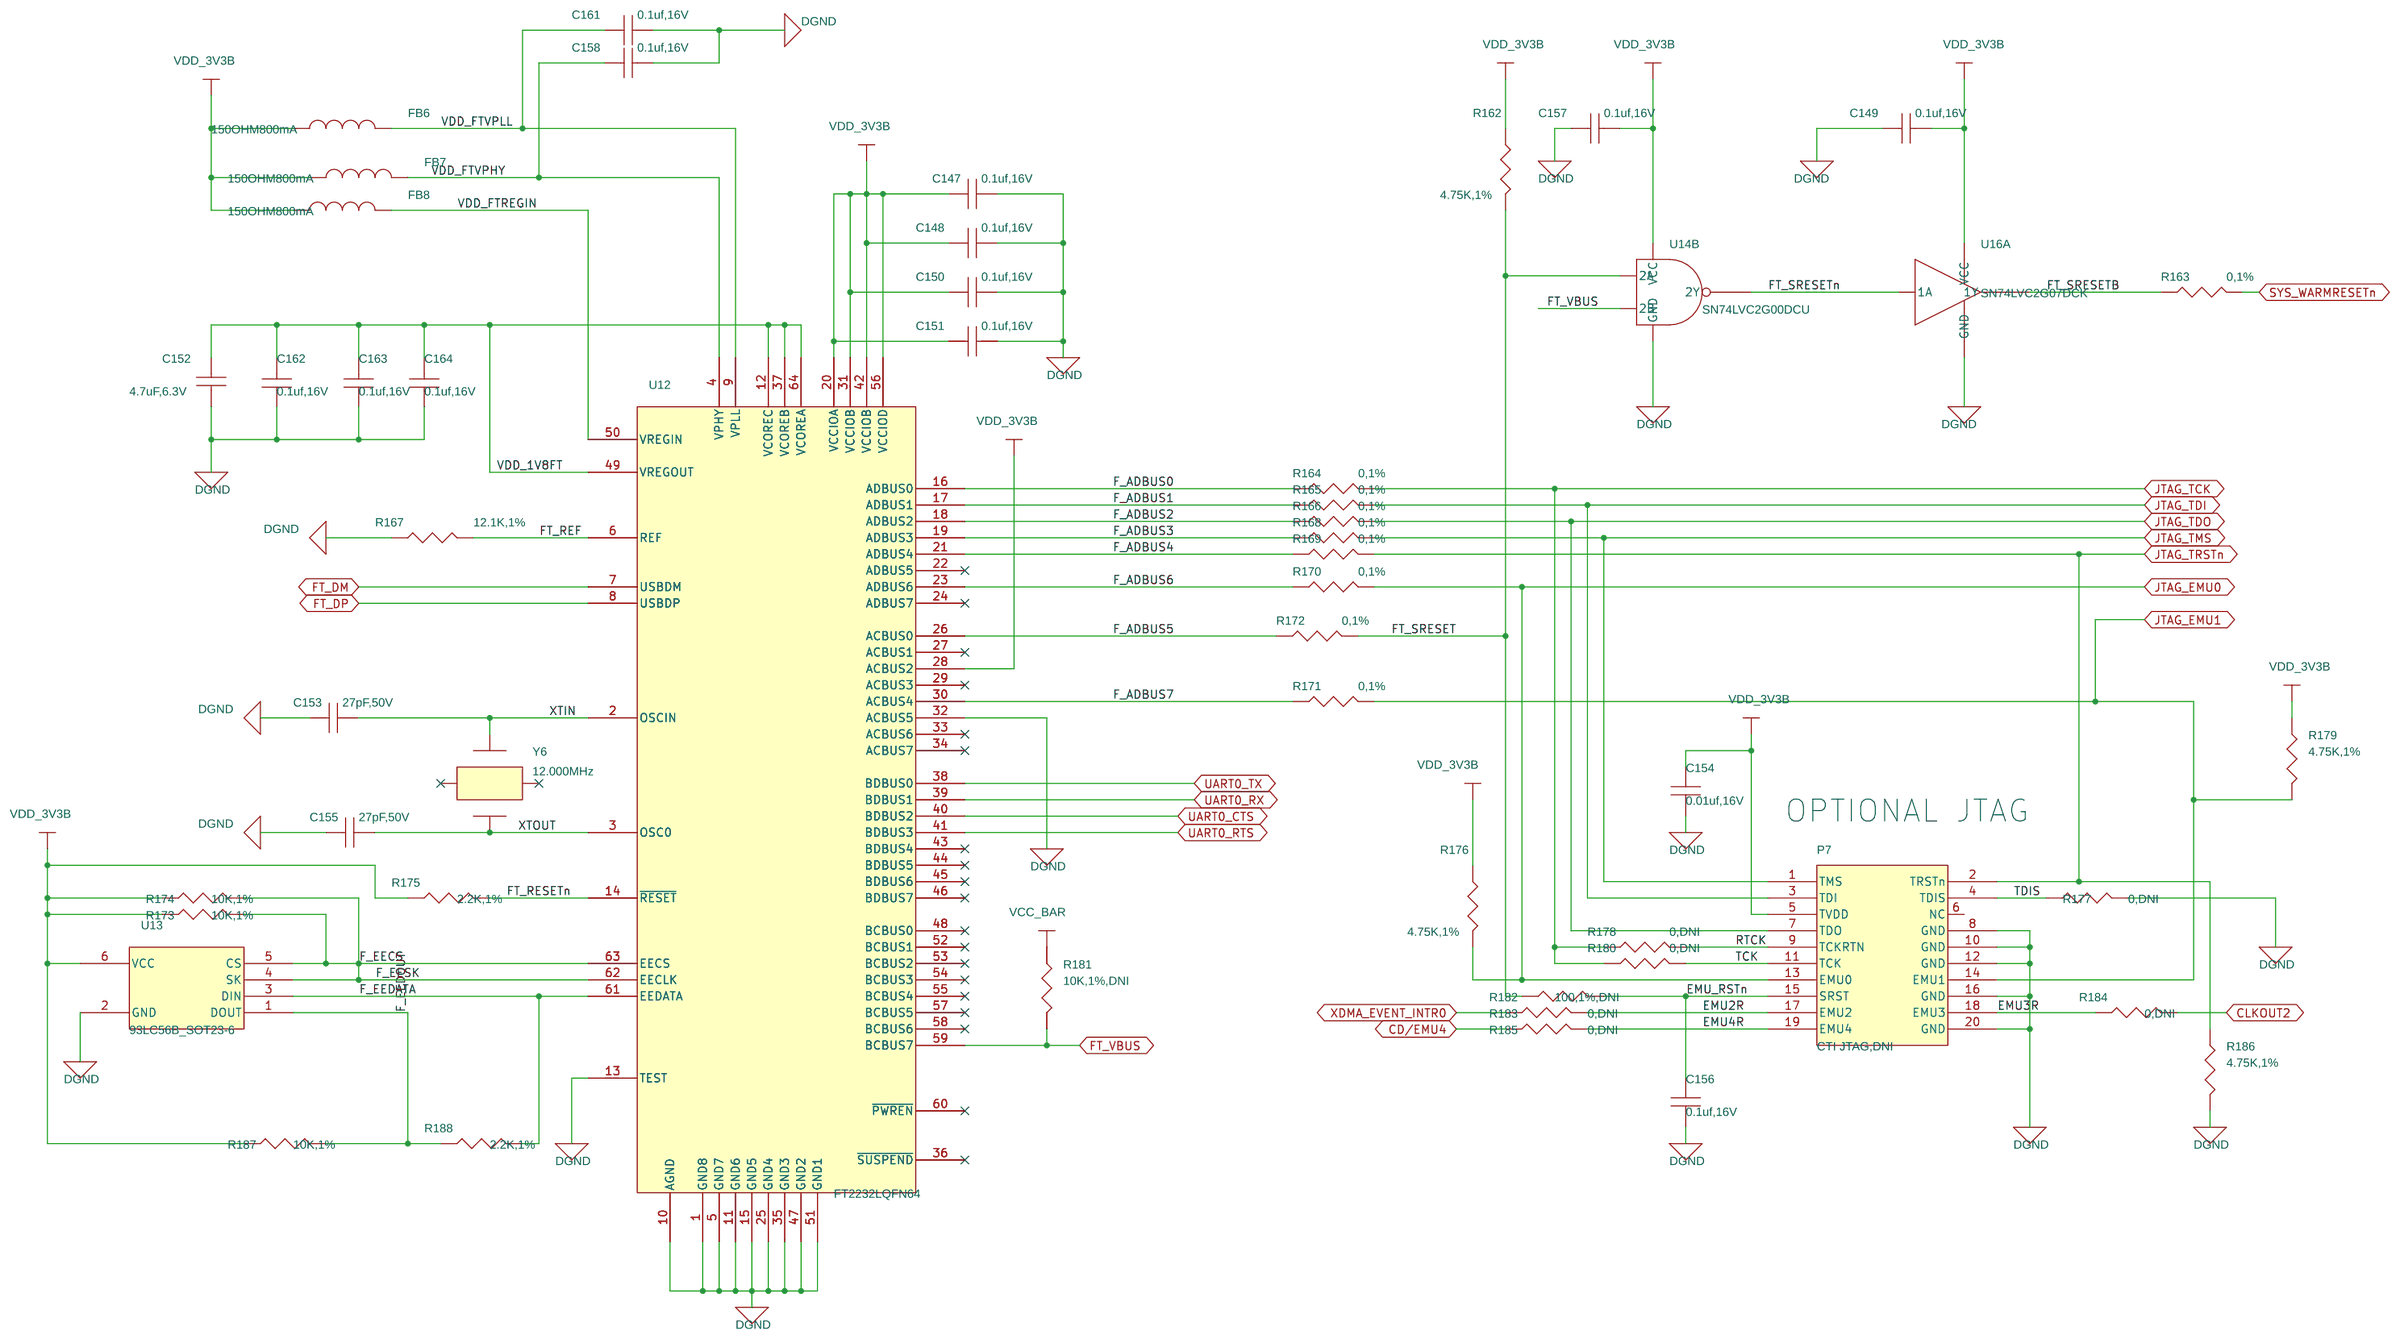
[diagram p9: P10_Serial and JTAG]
11 P11_Exp Conn, uSD, and LDO: size B; title: BeagleBone Expansion Headers, SD/MMC.and LDO
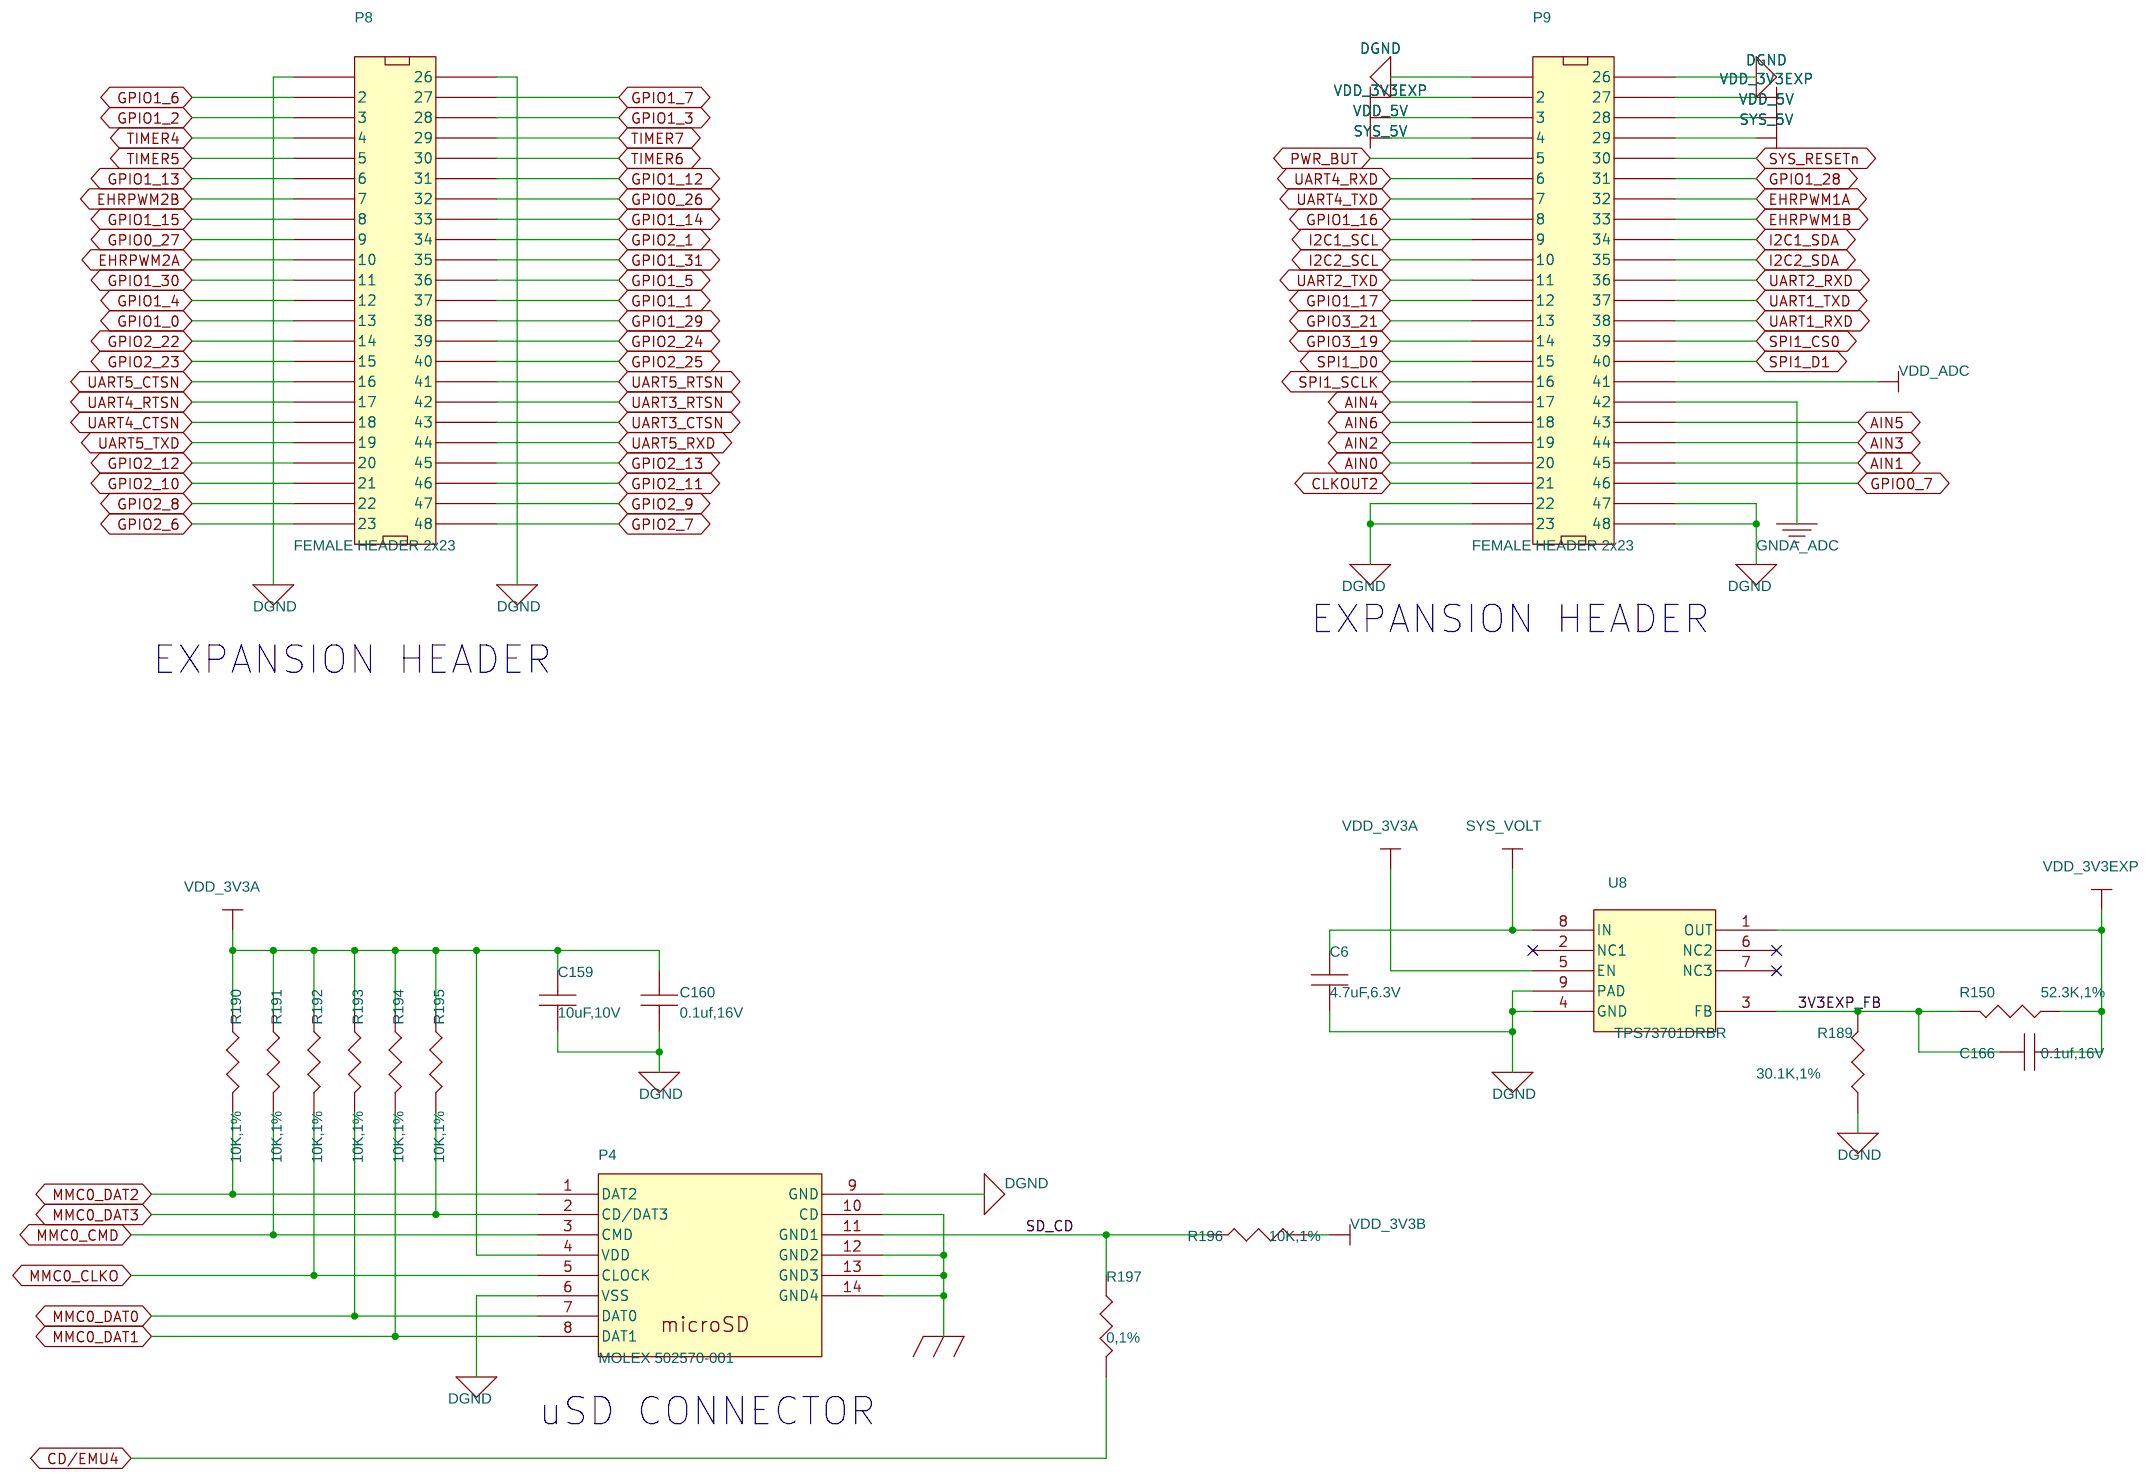
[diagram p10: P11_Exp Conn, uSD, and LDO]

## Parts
sheet P02_Power Management
C1  4.7uF,6.3V  [402]
C2  4.7uF,6.3V  [402]
C3  10uF,10V  [805]
C4  10uF,10V  [805]
C5  10uF,10V  [805]
C7  4.7uF,50V  [805]
C8  10uF,10V  [805]
C9  10uF,10V  [805]
C10  10uF,10V  [805]
C14  10uF,10V  [805]
C15  10uF,10V  [805]
C16  22uF,6.3V  [805]
C17  10uF,10V  [805]
C18  10uF,10V  [805]
C19  10uF,10V  [805]
C20  2.2uF,6.3V  [402]
C135  10uF,10V  [805]
C165  10uF,10V  [805]
D1  598-8170-107F  [LED0805-1]
L1  2.2uH,2.6A  [VLCF5020T]
L2  2.2uH,2.6A  [VLCF5020T]
L3  2.2uH,2.6A  [VLCF5020T]
MTG1  MHOLE  [MTGH200C125D_PL]
MTG2  MHOLE  [MTGH200C125D_PL]
MTG3  MHOLE  [MTGH200C125D_PL]
MTG4  MHOLE  [MTGH200C125D_PL]
P5  PJ-200A  [CONN3-PWR-PJ102A]
P6  HDR5x2  [HEADER10X2]
R1  4.75K,1%  [402]
R2  12.1K,1%  [402]
R3  .1,0805  [805]
R4  1.5K,5%  [402]
R6  470,5%  [402]
R7  1.5K,5%  [402]
R8  100K,1%  [402]
R9  100K,1%  [402]
R10  0,DNI  [402]
R11  0,1%  [402]
R12  0,1%  [402]
R13  0,1%  [402]
R14  0,1%  [402]
R15  0,1%  [402]
R19  0,1%  [402]
R28  0,1%  [402]
R121  0,1%  [402]
R203  100K,1%  [402]
R204  0,1%  [402]
TP1  TESTPT1  [tp1-8040]
TP14  TESTPT1  [TP60C_SMD]
TP15  TESTPT1  [TP60C_SMD]
TP17  TESTPT1  [TP60C_SMD]
TP18  TESTPT1  [TP60C_SMD]
U1  NCP349  [DFN6-1P6X2]
U2  TPS65217b  [U_48_RSL]
sheet P03_AM335x Sheet 1 of 3
C21  0.01uf,16V,DNI  [402]
C22  0.01uf,16V,DNI  [402]
C23  25pF,50V  [805]
C24  25pF,50V  [805]
C25  0.01uf,16V  [402]
C26  18pF,50V  [402]
C27  18pF,50V  [402]
R17  1.1K,1%,DNI  [402]
R18  12.1K,1%  [402]
R20  100K,1%  [402]
R21  1M,1%  [402]
R22  0,1%  [402]
R23  10K,1%  [402]
R24  0,1%  [402]
R25  33,0402  [402]
R26  33,0402  [402]
R27  0,1%  [402]
R29  33,0402  [402]
R30  33,0402  [402]
R31  33,0402  [402]
R32  33,0402  [402]
R33  33,0402  [402]
R34  33,0402  [402]
R35  33,0402  [402]
R36  33,0402  [402]
R37  33,0402  [402]
R38  33,0402  [402]
R39  33,0402  [402]
R40  33,0402  [402]
R41  33,0402  [402]
R42  33,0402  [402]
R43  33,0402  [402]
R44  33,0402  [402]
R45  33,0402  [402]
R46  33,0402  [402]
R47  33,0402  [402]
R48  33,0402  [402]
R49  33,0402  [402]
R50  33,0402  [402]
R51  33,0402  [402]
R52  33,0402  [402]
R53  33,0402  [402]
R54  33,0402  [402]
R55  33,0402  [402]
R56  33,0402  [402]
R57  33,0402  [402]
R58  33,0402  [402]
R59  33,0402  [402]
R60  33,0402  [402]
R61  33,0402  [402]
R62  33,0402  [402]
R63  33,0402  [402]
R64  33,0402  [402]
R65  33,0402  [402]
R66  33,0402  [402]
R67  33,0402  [402]
R68  33,0402  [402]
R69  33,0402  [402]
R70  33,0402  [402]
R71  33,0402  [402]
R72  33,0402  [402]
R73  33,0402  [402]
R74  2.2K,1%  [402]
R75  2.2K,1%  [402]
R76  49.9,1%  [402]
R141  10K,1%  [402]
R143  0,1%,DNI  [402]
TP3  TESTPT1  [TP60C_SMD]
U5  AM335X_ZCZ  [am33xx_15x15]  (sections A,B,C)
U17  SN74AUP2G08  [U_8_DCU]  (sections A,B)
Y1  32.768KHz MC-306  [MC-306]
Y2  24MHz,DNI  [SM_CRY_SCC18]
Y3  24MHz  [XTAL4_3P2X2P5_SMD]
sheet P04_AM335x Sheet 2 of 3
C28  0.01uf,16V  [402]
C29  0.01uf,16V  [402]
C30  0.001uf,50V  [402]
R77  4.75K,1%  [402]
R78  0,1%  [402]
R201  33,0402  [402]
TP4  TESTPT1  [TP60C_SMD]
sheet P05_AM335x Page 3 of 3
C31  10uF,10V  [805]
C32  10uF,10V  [805]
C33  0.01uf,16V  [402]
C34  0.01uf,16V  [402]
C35  0.01uf,16V  [402]
C36  0.01uf,16V  [402]
C37  0.01uf,16V  [402]
C38  0.01uf,16V  [402]
C39  0.01uf,16V  [402]
C40  0.01uf,16V  [402]
C41  0.01uf,16V  [402]
C42  0.01uf,16V  [402]
C43  0.01uf,16V  [402]
C44  10uF,10V  [805]
C45  0.01uf,16V  [402]
C46  0.01uf,16V  [402]
C47  0.01uf,16V  [402]
C48  0.01uf,16V  [402]
C49  0.01uf,16V  [402]
C50  10uF,10V  [805]
C51  0.01uf,16V  [402]
C52  0.01uf,16V  [402]
C53  0.01uf,16V  [402]
C54  0.01uf,16V  [402]
C55  0.01uf,16V  [402]
C56  0.01uf,16V  [402]
C57  0.01uf,16V  [402]
C58  0.01uf,16V  [402]
C59  0.01uf,16V  [402]
C60  0.01uf,16V  [402]
C61  0.01uf,16V  [402]
C62  0.01uf,16V  [402]
C63  0.01uf,16V  [402]
C64  0.01uf,16V  [402]
C65  0.01uf,16V  [402]
C66  0.01uf,16V  [402]
C67  0.01uf,16V  [402]
C68  0.01uf,16V  [402]
C69  10uF,10V  [805]
C70  0.01uf,16V  [402]
C71  0.01uf,16V  [402]
C72  0.01uf,16V  [402]
C73  0.01uf,16V  [402]
C74  0.01uf,16V  [402]
C75  0.01uf,16V  [402]
C76  0.01uf,16V  [402]
C77  0.01uf,16V  [402]
C78  0.01uf,16V  [402]
C79  0.01uf,16V  [402]
C80  0.01uf,16V  [402]
C81  0.01uf,16V  [402]
C82  0.01uf,16V  [402]
C83  1uF,10V  [402]
C84  1uF,10V  [402]
C85  1uF,10V  [402]
C86  0.01uf,16V  [402]
C87  0.01uf,16V  [402]
C88  0.01uf,16V  [402]
C89  10uF,10V  [805]
C90  0.01uf,16V  [402]
C91  0.01uf,16V  [402]
C92  0.01uf,16V  [402]
C93  0.01uf,16V  [402]
C94  0.01uf,16V  [402]
C95  0.01uf,16V  [402]
C96  0.01uf,16V  [402]
C97  1uF,10V  [402]
C98  0.01uf,16V  [402]
C99  0.01uf,16V  [402]
FB1  150OHM800mA  [sm-7351-ind-0805]
FB2  150OHM800mA  [sm-7351-ind-0805]
FB3  150OHM800mA  [sm-7351-ind-0805]
R79  10K,1%  [402]
TP5  TESTPT1  [TP60C_SMD]
TP6  TESTPT1  [TP60C_SMD]
sheet P06_LED, Config, & Reset
C100  4.7uF,6.3V  [402]
C101  1uF,10V,DNI  [402]
D2  598-8170-107F  [LED0805-1]
D3  598-8170-107F  [LED0805-1]
D4  598-8170-107F  [LED0805-1]
D5  598-8170-107F  [LED0805-1]
FB4  150OHM800mA  [sm-7351-ind-0805]
Q1  DMC56404  [SMini6-F3-B]  (sections A,B)
Q2  DMC56404  [SMini6-F3-B]  (sections A,B)
R80  100K,1%  [402]
R81  100K,1%  [402]
R82  100K,1%  [402]
R83  100K,1%,DNI  [402]
R84  100K,1%  [402]
R85  100K,1%,DNI  [402]
R86  100K,1%,DNI  [402]
R87  100K,1%,DNI  [402]
R88  100K,1%,DNI  [402]
R89  100K,1%,DNI  [402]
R90  100K,1%,DNI  [402]
R91  100K,1%,DNI  [402]
R92  100K,1%,DNI  [402]
R93  100K,1%,DNI  [402]
R94  100K,1%  [402]
R95  100K,1%,DNI  [402]
R96  470,5%  [402]
R97  470,5%  [402]
R98  470,5%  [402]
R99  470,5%  [402]
R100  100K,1%,DNI  [402]
R101  100K,1%,DNI  [402]
R102  100K,1%,DNI  [402]
R103  100K,1%  [402]
R104  100K,1%,DNI  [402]
R105  100K,1%  [402]
R106  100K,1%  [402]
R107  100K,1%  [402]
R108  100K,1%  [402]
R109  100K,1%  [402]
R110  100K,1%  [402]
R111  100K,1%  [402]
R112  100K,1%  [402]
R113  100K,1%  [402]
R114  100K,1%,DNI  [402]
R115  100K,1%  [402]
R116  100K,1%  [402]
R117  100K,1%  [402]
R118  100K,1%  [402]
R119  100K,1%  [402]
S1  B3U-1100  [SW3_4X2P5]
TP10  TESTPT1  [TP60C_SMD]
TP11  TESTPT1  [TP60C_SMD]
TP12  TESTPT1  [TP60C_SMD]
TP13  TESTPT1  [TP60C_SMD]
sheet P07_Memory
C102  0.1uf,16V  [402]
C103  0.01uf,16V  [402]
C104  0.01uf,16V  [402]
C105  0.01uf,16V  [402]
C106  0.01uf,16V  [402]
C107  0.01uf,16V  [402]
C108  0.01uf,16V  [402]
C109  0.01uf,16V  [402]
C110  0.01uf,16V  [402]
C111  0.01uf,16V  [402]
C112  0.01uf,16V  [402]
C113  0.01uf,16V  [402]
C114  0.01uf,16V  [402]
C115  0.01uf,16V  [402]
C116  22uF,6.3V  [805]
C117  0.01uf,16V  [402]
C118  0.01uf,16V  [402]
R120  0,1%  [402]
R210  10K,1%,DNI  [402]
U6  MT47H128M16RT-25E:C  [BGA84_8X12P5_P8MM]
U7  CAT24C256W  [SOIC_8]
sheet P08_Ethernet and USB Host
C119  0.1uf,16V  [402]
C120  0.1uf,16V  [402]
C121  4.7uF,6.3V  [402]
C122  0.1uf,16V  [402]
C123  0.1uf,16V  [402]
C124  470pF  [0603]
C125  1uF,10V  [402]
C126  15pF,DNI  [402]
C127  15pF,DNI  [402]
C128  15pF,DNI  [402]
C129  15pF,DNI  [402]
C130  0.022uF,10V  [402]
C131  30pF,50V  [402]
C132  30pF,50V  [402]
C133  100uF,6.3V  [6032]
C134  0.01uf,16V  [402]
FB5  150OHM800mA  [sm-7351-ind-0805]
P2  USB-A Conn. - 87520-xx1xx  [usb_a_sh]
P10  WE_7499010211A  [RJ45-7499010211A]
R5  10K,1%,DNI  [402]
R16  470,5%  [402]
R122  10K,1%  [402]
R123  10K,1%  [402]
R124  10K,1%  [402]
R125  10K,1%  [402]
R126  10K,1%,DNI  [402]
R127  10K,1%,DNI  [402]
R128  470,5%  [402]
R129  49.9,1%  [402]
R130  49.9,1%  [402]
R131  1.5K,5%  [402]
R132  100,1%  [402]
R133  49.9,1%  [402]
R134  49.9,1%  [402]
R135  100,1%  [402]
R136  100,1%  [402]
R137  100,1%  [402]
R138  .1,0805  [805]
R139  100,1%  [402]
R140  1M,1%,DNI  [402]
R142  0,1%  [402]
R144  10,1%  [402]
R145  12.1K,1%  [402]
R146  0,1%  [402]
R147  10K,1%  [402]
R148  10K,1%  [402]
R153  100,1%  [402]
R198  10K,1%,DNI  [402]
R199  0,1%  [402]
R200  0,1%,DNI  [402]
R205  100,1%  [402]
R206  100,1%  [402]
R207  100,1%  [402]
R208  100,1%  [402]
R209  10,1%,DNI  [402]
R211  10K,1%,DNI  [402]
R212  10K,1%  [402]
R213  10K,1%,DNI  [402]
R214  10K,1%  [402]
R215  10K,1%,DNI  [402]
R216  10K,1%  [402]
R219  10K,1%,DNI  [402]
U9  TPS2051 (DGN)  [DGN-16X60]
U10  TPD4S012  [U_6_DRY]
U15  LAN8710A  [QFN32_5X5MM_EP3P3MM]
Y4  25.000MHz  [XTAL2_5X3P2_SMD]
sheet P09_USB Port Concentrator
C136  0.1uf,16V  [402]
C137  18pF,50V  [402]
C138  0.1uf,16V  [402]
C139  4.7uF,6.3V  [402]
C140  0.1uf,16V  [402]
C141  0.1uf,16V  [402]
C142  0.1uf,16V  [402]
C143  0.1uf,16V  [402]
C144  18pF,50V  [402]
C145  0.1uf,16V,DNI  [402]
C146  0.1uf,16V,DNI  [402]
P3  mini USB-B  [usb-mini-smt-num]
R149  100K,1%  [402]
R151  100K,1%  [402]
R152  4.75K,1%  [402]
R154  10K,1%,DNI  [402]
R155  10K,1%,DNI  [402]
R156  100K,1%  [402]
R157  12.1K,1%  [402]
R158  10K,1%  [402]
R159  100K,1%  [402]
R160  1M,1%,DNI  [402]
R161  0,1%  [402]
TP7  TESTPT1  [TP60C_SMD]
TP8  TESTPT1  [TP60C_SMD]
U11  USB2412_QFN28_MKTG  [QFN28_5x5]
U16  SN74LVC2G07DCK  [DCK6_2P15X1P4]  (sections A,B)
Y5  24MHz  [XTAL4_3P2X2P5_SMD]
sheet P10_Serial and JTAG
C147  0.1uf,16V  [402]
C148  0.1uf,16V  [402]
C149  0.1uf,16V  [402]
C150  0.1uf,16V  [402]
C151  0.1uf,16V  [402]
C152  4.7uF,6.3V  [402]
C153  27pF,50V  [402]
C154  0.01uf,16V  [402]
C155  27pF,50V  [402]
C156  0.1uf,16V  [402]
C157  0.1uf,16V  [402]
C158  0.1uf,16V  [402]
C161  0.1uf,16V  [402]
C162  0.1uf,16V  [402]
C163  0.1uf,16V  [402]
C164  0.1uf,16V  [402]
FB6  150OHM800mA  [sm-7351-ind-0805]
FB7  150OHM800mA  [sm-7351-ind-0805]
FB8  150OHM800mA  [sm-7351-ind-0805]
P7  CTI JTAG,DNI  [HEADER10X2_SMD]
R162  4.75K,1%  [402]
R163  0,1%  [402]
R164  0,1%  [402]
R165  0,1%  [402]
R166  0,1%  [402]
R167  12.1K,1%  [402]
R168  0,1%  [402]
R169  0,1%  [402]
R170  0,1%  [402]
R171  0,1%  [402]
R172  0,1%  [402]
R173  10K,1%  [402]
R174  10K,1%  [402]
R175  2.2K,1%  [402]
R176  4.75K,1%  [402]
R177  0,DNI  [402]
R178  0,DNI  [402]
R179  4.75K,1%  [402]
R180  0,DNI  [402]
R181  10K,1%,DNI  [402]
R182  100,1%,DNI  [402]
R183  0,DNI  [402]
R184  0,DNI  [402]
R185  0,DNI  [402]
R186  4.75K,1%  [402]
R187  10K,1%  [402]
R188  2.2K,1%  [402]
U12  FT2232LQFN64  [LQFP64_10X10]
U13  93LC56B_SOT23-6  [SOT23-6]
U14  SN74LVC2G00DCU  [U_8_DCU]  (sections A,B)
Y6  12.000MHz  [XTAL4_3P2X5SMD]
sheet P11_Exp Conn, uSD, and LDO
C6  4.7uF,6.3V  [402]
C159  10uF,10V  [805]
C160  0.1uf,16V  [402]
C166  0.1uf,16V  [402]
P4  MOLEX 502570-001  [CON8SMD-MICRO_SD_14P3X15P9]
P8  FEMALE HEADER 2x23  [HEADER23X2]
P9  FEMALE HEADER 2x23  [HEADER23X2]
R150  52.3K,1%  [402]
R189  30.1K,1%  [402]
R190  10K,1%  [402]
R191  10K,1%  [402]
R192  10K,1%  [402]
R193  10K,1%  [402]
R194  10K,1%  [402]
R195  10K,1%  [402]
R196  10K,1%  [402]
R197  0,1%  [402]
U8  TPS73701DRBR  [drb8-14x33-pad]

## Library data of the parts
C1 C2 C6 C100 C121 C139 C152 = CAP_4.7uF_X5R_6.3V_10%_0603
C3-C5 C8-C10 C14 C15 C17-C19 C31 C32 C44 C50 C69 C89 C135 C159 C165 = CAP_10uF_Y5V_10V_10%_0805
C7 = CAP_4.7uF_X5R_50V_10%_0805
C16 C116 = CAP_22uF_X5R_6.3V_120%_0805
C20 = CAP_2.2uF_X5R_6.3V_10%_0402
D1-D5 = LED_LTST-C150GKT
L1-L3 = IND_2.2uH_2.6A_10%_SMD
MTG1-MTG4 = MHOLE
P5 = Power_Jack
P6 = HDR_10_F_2_0.1
R1 R2 R23 R79 R142 R144 R147 R148 R154 R155 R158 R173 R174 R181 R187 R190-R196 R219 = RES_10K_1_16W_1%_0402
R3 R138 = RES_0.1_0805
R4 R7 R131 = RES_1.5K_1_16W_5%_0402
R6 R16 R96-R99 R128 = RES_470_1_10W_5%_0402
R8 R9 R18 R20 R80-R95 R100-R119 R141 R143 R146 R149 R151 R152 R156 R159 R203 = RES_100K_1_16W_1%_0402
R5 R10 R12 R13 R19 R77 R121-R127 R162 R176 R179 R186 R198 R211-R216 = RES_4.75K_1_16W_1%_0402
R11 R14 R15 R22 R24 R27 R28 R78 R161 R163-R166 R168-R172 R177 R178 R180 R183-R185 R197 R199 R200 R204 R210 = RES_0_1_16W_1%_0402
TP1 TP3-TP8 TP10-TP15 TP17 TP18 = TESTPT1
U1 = PWR_NCP349_6-DFN
U2 = PWR_TPS65217_2
C21 C22 C25 C28 C29 C33-C43 C45-C49 C51-C68 C70-C82 C86-C88 C90-C96 C98 C99 C103-C115 C117 C118 C134 C154 = CAP_0.01uf_X7R_16V_10%_0402
C23 C24 = CAP_25PF_NPO_100V_5%_0805
C26 C27 C137 C144 C153 C155 = CAP_18PF_COG_50V_5%_0402
R17 = RES_1.1K_1_16W_1%_0402
R21 R140 R160 = RES_1M_1_16W_1%_0402
R25 R26 R29-R73 R201 = RES_33_0402
R74 R75 R175 R188 = RES_2.2K_1_16W_1%_0402
R76 R129 R130 R133 R134 = RES_4.7K_0402
U5 = IC_AM335X_ZCE_1
U17 = IC_SN74AUP2G08_8-VSSOP
Y1 = CRYS_32_768KHz_SMD32
Y2 Y3 Y5 = CRYS_24MHz_SCC
C30 = CAP_0.001_X7R_50V_5%_0402
C83-C85 C97 C101 C125 = CAP_1.0UF_X5R_10V_10%_0402
FB1-FB8 = FER_180_200_0
Q1 Q2 = RN1907: ATLStockNo2: 2130.01
S1 = SW_DP_MOM
C102 C119 C120 C122 C123 C136 C138 C140-C143 C145-C151 C156-C158 C160-C164 C166 = CAP_0.1uF_X7R_16V_10%_0402
R120 = ZeroOhmResistor1_16W0402
U6 = MEM_MT47H64M16_FBGA84_1
U7 = CAT24C256W
C124 = 470pF_5%_50V_C0G_0603_0
C126-C129 = CAP_0402_100pF_COG_50V
C130 = CAP_0402_0.1uf_X5R_10V
C131 C132 = CAP_30PF_COG_50V_5%_0402
C133 = CAP_100UF_TANT_6.3V_3528-21
P2 = CONN_54819-0578_2
P10 = CONN_RJ45_MAG_WE_0
R132 R135-R137 R139 R182 = RES_100_1_10W_5%_0402
R145 R157 R167 = RES_12.1K_1_16W_1%_0402
R153 R205-R209 = 100-1_10W-1%-0603_4
U9 = TPS2061_0
U10 = PROT_TPD4S012
U15 = LAN8710_QFN32_1
Y4 = Suntsu_ITEMP_25MHz__0.005%_20pf
P3 = MINI-USB-AB-SOCKET
U11 = USB2412_QFN28_MKTG_2
U16 = IC_SN74LVC2G07DCK
P7 = HDR_10x2_CJTAG
U12 = IC_FT2232H_LQFP64
U13 = IC_93C46B_SSOT23-6
U14 = IC_SN74LVC2G38_8-VSSOP
Y6 = XTAL_12MHZ_HC-49SMT_0
P4 = microSD_CONN_2
P8 P9 = HDR_46_F_2_0.1_0.1
R150 = RES_0: TN: 272-0664-000
R189 = RES_0: TN: 272-0187-000
U8 = TPS73701_0

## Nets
3V3EXP_FB: C166.1 R150.1(P1) R189.1(P1) U8.3(FB)
AGND: R15.1 U2.41(AGND)
DGND: C1.2 C2.2 C3.1 C4.1 C5.1 C6.2 C7.2 C8.1 C9.1 C10.1 C14.1 C15.1 C16.2 C17.1 C18.1 C19.1 C20.2 C21.2 C22.2 C25.2 C31.1 C32.1 C33.2 C34.2 C35.2 C36.2 C37.2 C38.2 C39.2 C40.2 C41.2 C42.2 C43.1 C44.1 C45.2 C46.2 C47.2 C48.2 C49.2 C50.1 C51.2 C52.1 C53.2 C54.2 C55.2 C56.2 C57.2 C58.1 C59.1 C60.2 C61.2 C62.1 C63.1 C64.1 C65.1 C66.1 C67.1 C68.1 C69.2 C70.1 C71.1 C72.2 C73.2 C74.2 C75.2 C76.2 C77.2 C78.2 C79.2 C80.2 C81.2 C82.2 C83.2 C84.2 C85.2 C86.2 C88.2 C89.1 C90.2 C91.2 C92.2 C93.2 C94.2 C95.2 C96.2 C97.2 C98.2 C99.2 C100.2 C101.2 C102.2 C103.2 C104.2 C105.2 C106.2 C107.2 C108.2 C109.2 C110.2 C111.2 C112.2 C113.2 C114.2 C115.2 C116.2 C117.2 C118.2 C119.2 C120.2 C121.2 C122.2 C123.2 C124.2 C125.2 C126.2 C127.2 C128.2 C129.2 C130.2 C131.2 C132.2 C133.2 C134.2 C135.1 C136.2 C137.1 C138.2 C139.2 C140.2 C141.2 C142.2 C143.2 C144.1 C145.2 C146.2 C147.2 C148.2 C149.1 C150.2 C151.2 C152.2 C153.1 C154.2 C155.1 C156.2 C157.1 C158.2 C159.2 C160.2 C161.2 C162.1 C163.1 C164.1 C165.1 D1.1(C) FB3.2 P2.4(P4) P3.5(G1) P4.6(VSS) P4.9(GND) P5.2 P7.8(GND) P7.10(GND) P7.12(GND) P7.16(GND) P7.20(GND) P8.1 P8.2(26) P9.1 P9.2(26) P9.43(22) P9.44(47) P9.45(23) P9.46(48) P10.8(GND) Q1.1(4) Q1.4 Q2.1(4) Q2.4 R1.1 R5.2 R9.1 R15.2 R16.1 R18.2 R20.2 R75.2 R76.1 R79.1 R100.2 R101.2 R102.2 R103.2 R104.2 R105.2 R106.2 R107.2 R108.2 R109.2 R110.2 R111.2 R112.2 R113.2 R114.2 R115.2 R116.2 R117.2 R118.2 R119.2 R125.2 R127.2 R128.1 R138.1 R145.2 R146.2 R147.2 R151.2 R157.2 R158.2 R159.2 R161.1 R167.1 R177.2 R186.2 R189.2(P2) R198.2 R212.2 R214.2 R216.2 R219.2 S1.1(A1) TP1.1(TP) U1.2(GND) U1.6(~{EN}) U2.30(PGND) U2.49(PPAD) U5.A1(VSS) U5.A18(VSS) U5.F8(VSS) U5.G8(VSS) U5.G9(VSS) U5.G11(VSS) U5.G12(VSS) U5.H6(VSS) U5.H7(VSS) U5.H8(VSS) U5.H9(VSS) U5.H10(VSS) U5.H12(VSS) U5.J6(VSS) U5.J7(VSS) U5.J8(VSS) U5.J9(VSS) U5.J10(VSS) U5.J11(VSS) U5.K7(VSS) U5.K9(VSS) U5.K10(VSS) U5.K11(VSS) U5.L10(VSS) U5.L11(VSS) U5.L12(VSS) U5.L13(VSS) U5.M6(VSS) U5.M7(VSS) U5.M8(VSS) U5.M9(VSS) U5.M10(VSS) U5.M12(VSS) U5.M14(VSSA_USB) U5.N7(VSS) U5.N10(VSS) U5.N11(VSS) U5.N14(VSSA_USB) U5.V1(VSS) U5.V18(VSS) U6.A3(VSS) U6.A7(VSSQ) U6.B2(VSSQ) U6.B8(VSSQ) U6.D2(VSSQ) U6.D8(VSSQ) U6.E3(VSS) U6.E7(VSSQ) U6.F2(VSSQ) U6.F8(VSSQ) U6.H2(VSSQ) U6.H8(VSSQ) U6.J3(VSS) U6.J7(VSSDL) U6.N1(VSS) U6.P9(VSS) U7.1(A0) U7.2(A1) U7.3(A2) U7.4(VSS) U8.4(GND) U8.9(PAD) U9.1(GND) U9.9(PAD) U10.4(GND) U11.6(TEST) U11.29(VSS(FLAG)) U12.1(GND8) U12.5(GND7) U12.10(AGND) U12.11(GND6) U12.13(TEST) U12.15(GND5) U12.25(GND4) U12.32(ACBUS5) U12.35(GND3) U12.47(GND2) U12.51(GND1) U13.2(GND) U14.4(GND) U15.33(GND_EP) U16.2(GND) U17.4(GND)
GND_EARTH: MTG1.1(TP) MTG2.1(TP) MTG3.1(TP) MTG4.1(TP) P2.5(SHELD1) P2.6(PAD4) P3.6(G3) P3.7(G2) P3.8(G5) P3.9(G4) P4.10(CD) P4.12(GND2) P4.13(GND3) P4.14(GND4) P10.13(SHD1) P10.14(SHD2) R138.2 S1.3(A3)
GND_OSC0: C26.2 C27.2 U5.V11(VSS_OSC0)
GND_OSC1: C23.1 C24.1 U5.A5(VSS_RTC)
GNDA_ADC: C28.2 C29.2 C30.2 C87.2 FB3.1 P9.34(42) U5.A9(VREFN) U5.E8(VSSA_ADC)
VBUS_DET: R149.2 R151.1 U11.18(VBUS_DET)
VDD_1V8: C16.1 C72.1 C74.1 C75.1 C76.1 C77.1 C78.1 C79.1 C80.1 C82.1 C86.1 FB1.1 FB2.2 R12.2 R14.1 TP15.1(TP) U5.D10(VDDS_SRAM_MPU_BB) U5.E6(VDDS) U5.E7(VDDS_PLL_DDR) U5.E9(VDDS_SRAM_CORE_BG) U5.E14(VDDS) U5.F9(VDDS) U5.K13(VDDS) U5.N6(VDDS) U5.N16(VDDA1P8V_USB0) U5.P9(VDDS) U5.P14(VDDS) U5.R16(VDDA1P8V_USB1)
VDD_1V8FT: C152.1 C162.2 C163.2 C164.2 U12.12(VCOREC) U12.37(VCOREB) U12.49(VREGOUT) U12.64(VCOREA)
VDD_3V3A: C42.1 C43.2 C51.1 C52.2 C56.1 C57.1 C58.2 C59.2 C60.1 C61.1 C62.2 C63.2 C64.2 C65.2 C66.2 C67.2 C68.2 C69.1 C70.2 C71.2 C81.1 C159.1 C160.1 C165.2 P4.4(VDD) R4.1 R7.1 R19.2 R23.1 R80.1 R81.1 R82.1 R83.1 R84.1 R85.1 R86.1 R87.1 R88.1 R89.1 R90.1 R91.1 R92.1 R93.1 R94.1 R95.1 R190.1 R191.1 R192.1 R193.1 R194.1 R195.1 U2.18(VIO) U5.E10(VDDSHV6) U5.E11(VDDSHV6) U5.E12(VDDSHV6) U5.E13(VDDSHV6) U5.F14(VDDSHV6) U5.G14(VDDSHV6) U5.H14(VDDSHV4) U5.J14(VDDSHV4) U5.K14(VDDSHV5) U5.L14(VDDSHV5) U5.N5(VDDSHV6) U5.N15(VDDA3P3V_USB0) U5.P5(VDDSHV6) U5.P6(VDDSHV6) U5.P7(VDDSHV1) U5.P8(VDDSHV1) U5.P10(VDDSHV2) U5.P11(VDDSHV2) U5.P12(VDDSHV3) U5.P13(VDDSHV3) U5.R15(VDDA3P3V_USB1) U8.5(EN)
VDD_3V3B: C102.1 C122.1 C123.1 C135.2 C138.1 C139.1 C140.1 C141.1 C142.1 C143.1 C147.1 C148.1 C149.2 C150.1 C151.1 C154.1 C157.2 FB5.1 FB6.1 FB7.1 FB8.1 P7.5(TVDD) R121.2 R122.2 R123.2 R124.2 R126.1 R131.1 R148.1 R154.1 R155.1 R156.1 R162.1 R173.1 R174.1 R175.1 R176.1 R179.1 R181.1 R187.1 R196.2 R203.1 R210.1 R211.2 R213.2 R215.2 U7.8(VCC) U11.4(VDD33) U11.10(VDDCRREF/VDD33) U11.14(VDD33) U11.20(VDD33) U11.27(VDDPLLREF/VDD33) U12.20(VCCIOA) U12.28(ACBUS2) U12.31(VCCIOB) U12.42(VCCIOB) U12.56(VCCIOD) U13.6(VCC) U14.8(VCC) U15.12(VDDIO) U16.5(VCC)
VDD_3V3EXP: C166.2 P9.3(2) P9.4(27) R150.2(P2) U8.1(OUT)
VDD_5V: P5.1 P9.5(3) P9.6(28) U1.1(IN1) U1.7(IN0)
VDD_ADC: C87.1 FB2.1 P9.32(41) R78.1 U5.D8(VDDA_ADC)
VDD_CORE: C14.2 C31.2 C32.2 C33.1 C34.1 C35.1 C36.1 C37.1 C38.1 C39.1 C40.1 C41.1 C48.1 C49.1 C50.2 C53.1 C54.1 C55.1 R13.2 TP17.1(TP) U5.F6(VDD_CORE1) U5.F7(VDD_CORE2) U5.G6(VDD_CORE3) U5.G7(VDD_CORE4) U5.G10(VDD_CORE5) U5.H11(VDD_CORE6) U5.J12(VDD_CORE7) U5.K6(VDD_CORE8) U5.K8(VDD_CORE9) U5.K12(VDD_CORE10) U5.L6(VDD_CORE11) U5.L7(VDD_CORE12) U5.L8(VDD_CORE13) U5.L9(VDD_CORE14) U5.M5(VPP) U5.M11(VDD_CORE15) U5.M13(VDD_CORE16) U5.N8(VDD_CORE17) U5.N9(VDD_CORE18) U5.N12(VDD_CORE19) U5.N13(VDD_CORE20)
VDD_FTREGIN: FB8.2 U12.50(VREGIN)
VDD_FTVPHY: C158.1 FB7.2 U12.4(VPHY)
VDD_FTVPLL: C161.1 FB6.2 U12.9(VPLL)
VDD_LED: C100.1 FB4.1 R96.1 R97.1 R98.1 R99.1
VDD_MPU: C15.2 C44.2 C45.1 C46.1 C47.1 R204.2 U5.F10(VDD_MPU1) U5.F11(VDD_MPU2) U5.F12(VDD_MPU3) U5.F13(VDD_MPU4) U5.G13(VDD_MPU5) U5.H13(VDD_MPU6) U5.J13(VDD_MPU7)
VDD_MPUON: TP5.1(TP) U5.A2(VDD_MPU_MON)
VDD_PHYA: C119.1 C120.1 C121.1 FB5.2 R129.2 R130.2 R133.2 R134.2 R142.2 U15.1(VDD2A) U15.27(VDD1A)
VDD_PLL: C73.1 C88.1 C99.1 FB1.2 U5.H15(VDDS_PLL_MPU) U5.R10(VDDS_PLL_CORE_LCD) U5.R11(VDDS_OSC)
VDD_RTC: C97.1 U5.D6(CAP_VDD_RTC)
VDDS_DDR: C89.2 C90.1 C91.1 C92.1 C93.1 C94.1 C95.1 C96.1 C103.1 C104.1 C105.1 C106.1 C107.1 C108.1 C109.1 C110.1 C111.1 C112.1 C113.1 C114.1 C115.1 C116.1 C117.1 R14.2 R74.1 TP18.1(TP) U5.E5(VDDS_DDR) U5.F5(VDDS_DDR) U5.G5(VDDS_DDR) U5.H5(VDDS_DDR) U5.J5(VDDS_DDR) U5.K5(VDDS_DDR) U5.L5(VDDS_DDR) U6.A1(VDD) U6.A9(VDDQ) U6.C1(VDDQ) U6.C3(VDDQ) U6.C7(VDDQ) U6.C9(VDDQ) U6.E1(VDD) U6.E9(VDDQ) U6.G1(VDDQ) U6.G3(VDDQ) U6.G7(VDDQ) U6.G9(VDDQ) U6.J1(VDDL) U6.J9(VDD) U6.M9(VDD) U6.R1(VDD)
AIN0: P9.39(20) U5.B6(AIN0)
AIN1: P9.40(45) U5.C7(AIN1)
AIN2: P9.37(19) U5.B7(AIN2)
AIN3: P9.38(44) U5.A7(AIN3)
AIN4: P9.33(17) U5.C8(AIN4)
AIN5: P9.36(43) U5.B8(AIN5)
AIN6: P9.35(18) U5.A8(AIN6)
AIN7: R8.1 R9.2 U5.C9(AIN7)
BAT: C3.2 P6.1 P6.2 U2.4(BAT1) U2.5(BAT2)
BAT_SENSE: P6.3 U2.6(BAT_SENSE)
BAT_TEMP: P6.4 U2.11(TS)
BL_IN: P6.8 U2.37(L4)
BL_ISET1: P6.6 U2.35(ISET1)
BL_ISET2: P6.5 U2.36(ISET2)
BL_OUT: C7.1 P6.7 U2.38(FB_WLED)
BL_SINK1: P6.9 U2.34(ISINK1)
BL_SINK2: P6.10 U2.33(ISINK2)
CAP_VBB_MPU: C85.1 U5.C10(CAP_VBB_MPU)
CAP_VDD_SRAM_CORE: C83.1 U5.D9(CAP_VDD_SRAM_CORE)
CAP_VDD_SRAM_MPU: C84.1 U5.D11(CAP_VDD_SRAM_MPU)
CD/EMU4: R185.1 R197.2 U5.C15(SPI0_CS1/UART3_RXD/ECAP1_IN_PWM1_OUT/MMC0_POW/XDMA_EVENT_INTR2/MMC0_SDCD/EMU4/GPIO0_6)
CLKOUT2: P9.41(21) R184.2 U5.D14(EVENT_INTR1/TCLKIN/CLKOUT2/TIMER7/PR1PRU0_PRUR31_16/EMU3/GPIO0_20)
COL/CRS_DV/MODE2: R207.2 U15.15(COL/CRS_DV/MODE2)
CRFILT: C146.1 U11.9(CRFILT)
CRS_DV/MODE2: R122.1 R127.1 R139.2 U15.14(CRS)
DC_IN: C1.1 U1.4(OUT0) U1.5(OUT1) U2.10(AC)
DDR_A0: R29.1 U6.M8(A0)
DDR_A1: R25.1 U6.M3(A1)
DDR_A2: R30.1 U6.M7(A2)
DDR_A3: R26.1 U6.N2(A3)
DDR_A4: R31.1 U6.N8(A4)
DDR_A5: R32.1 U6.N3(A5)
DDR_A6: R33.1 U6.N7(A6)
DDR_A7: R34.1 U6.P2(A7)
DDR_A8: R35.1 U6.P8(A8)
DDR_A9: R36.1 U6.P3(A9)
DDR_A10: R37.1 U6.M2(A10)
DDR_A11: R38.1 U6.P7(A11)
DDR_A12: R39.1 U6.R2(A12)
DDR_A13: R40.1 R120.1(P1)
DDR_A13R: R120.2(P2) U6.R8((RFU)A13)
DDR_BA0: R41.1 U6.L2(BA0)
DDR_BA1: R42.1 U6.L3(BA1)
DDR_BA2: R43.1 U6.L1(BA2)
DDR_CASn: R64.1 U6.L7(CASn)
DDR_CKE: R62.1 U6.K2(CKE)
DDR_CLK: R60.1 U6.J8(CK)
DDR_CLKn: R61.1 U6.K8(CKn)
DDR_CSn: R63.1 U6.L8(CSn)
DDR_D0: R44.1 U6.G8(DQ0)
DDR_D1: R45.1 U6.G2(DQ1)
DDR_D2: R46.1 U6.H7(DQ2)
DDR_D3: R47.1 U6.H3(DQ3)
DDR_D4: R48.1 U6.H1(DQ4)
DDR_D5: R49.1 U6.H9(DQ5)
DDR_D6: R50.1 U6.F1(DQ6)
DDR_D7: R51.1 U6.F9(DQ7)
DDR_D8: R52.1 U6.C8(DQ8)
DDR_D9: R53.1 U6.C2(DQ9)
DDR_D10: R54.1 U6.D7(DQ10)
DDR_D11: R55.1 U6.D3(DQ11)
DDR_D12: R56.1 U6.D1(DQ12)
DDR_D13: R57.1 U6.D9(DQ13)
DDR_D14: R58.1 U6.B1(DQ14)
DDR_D15: R59.1 U6.B9(DQ15)
DDR_DQM0: R67.1 U6.F3(LDM)
DDR_DQM1: R70.1 U6.B3(UDM)
DDR_DQS0: R68.1 U6.F7(LDQS)
DDR_DQS1: R71.1 U6.B7(UDQS)
DDR_DQSN0: R69.1 U6.E8(LDQSn)
DDR_DQSN1: R72.1 U6.A8(UDQSn)
DDR_ODT: R73.1 U6.K9(ODT)
DDR_RASn: R65.1 U6.K7(RASn)
DDR_RESETN: TP3.1(TP) U5.G2(DDR_RESETN)
DDR_VREF: C118.1 R74.2 R75.1 U5.J4(VREFSSTL) U6.J2(VREF)
DDR_VTP: R76.2 U5.J3(DDR_VTP)
DDR_WEn: R66.1 U6.K3(WEn)
EHRPWM1A: P9.14(32) U5.U14(GPMC_A2/GMII2_TXD3/RGMII2_TD3/MMC2_DAT1/GPMC_A18/PR1_MII1_TXD2/EHRPWM1A/GPIO1_18)
EHRPWM1B: P9.16(33) U5.T14(GPMC_A3/GMII2_TXD2/RGMII2_TD2/MMC2_DAT2/GPMC_A19/PR1_MII1_TXD1/EHRPWM1B/GPIO1_19)
EHRPWM2A: P8.19(10) U5.U10(GPMC_AD8/LCD_DATA23/MMC1_DAT0/MMC2_DAT4/EHRPWM2A/PR1_MII_MT0_CLK//GPIO0_22)
EHRPWM2B: P8.13(7) U5.T10(GPMC_AD9/LCD_DATA22/MMC1_DAT1/MMC2_DAT5/EHRPWM2B/PR1_MII0_CRS//GPIO0_23)
EMU2R: P7.17(EMU2) R183.2
EMU3R: P7.18(EMU3) R184.1
EMU4R: P7.19(EMU4) R185.2
EMU_RSTn: C156.1 P7.15(SRST) R182.2
ENZ_KALDO_1P8V: R79.2 U5.B4(ENZ_KALDO_1P8V)
F_ADBUS0: R164.1 U12.16(ADBUS0)
F_ADBUS1: R165.1 U12.17(ADBUS1)
F_ADBUS2: R166.1 U12.18(ADBUS2)
F_ADBUS3: R168.1 U12.19(ADBUS3)
F_ADBUS4: R169.1 U12.21(ADBUS4)
F_ADBUS5: R172.1 U12.26(ACBUS0)
F_ADBUS6: R170.1 U12.23(ADBUS6)
F_ADBUS7: R171.1 U12.30(ACBUS4)
F_EECS: R173.2 U12.63(EECS) U13.5(CS)
F_EEDATA: R188.2 U12.61(EEDATA) U13.3(DIN)
F_EEDOUT: R187.2 R188.1 U13.1(DOUT)
F_EESK: R174.2 U12.62(EECLK) U13.4(SK)
FT_DM: U11.28(USBDM_DN1) U12.7(USBDM)
FT_DP: U11.1(USBDP_DN1) U12.8(USBDP)
FT_REF: R167.2 U12.6(REF)
FT_RESETn: R175.2 U12.14(~{RESET})
FT_SRESET: R162.2 R172.2 R182.1 U14.5(2A)
FT_SRESETB: R163.1 U16.6(1Y)
FT_SRESETn: U14.3(2Y) U16.1(1A)
FT_VBUS: R181.2 U11.7(PRTPWR1) U12.59(BCBUS7) U14.6(2B)
GPIO0_7: P9.42(46) U5.C18(ECAP0_IN_PWM0_OUT/UART3_TXD/SPI1_CS1/PR1_ECAP0_ECAP_CAPIN_APWM_O/SPI1_SCLK/MMC0_SDWP/XDMA_EVENT_INTR2/GPIO0_7)
GPIO0_26: P8.14(32) U5.T11(GPMC_AD10/LCD_DATA21/MMC1_DAT2/MMC2_DAT6/EHRPWM2_TRIPZONE_INPUT/PR1_MII0_TXEN//GPIO0_26)
GPIO0_27: P8.17(9) U5.U12(GPMC_AD11/LCD_DATA20/MMC1_DAT3/MMC2_DAT7/EHRPWM2_SYNCI_O/PR1_MII0_TXD3//GPIO0_27)
GPIO1_0: P8.25(13) U5.U7(GPMC_AD0/MMC1_DAT0//////GPIO1_0)
GPIO1_1: P8.24(37) U5.V7(GPMC_AD1/MMC1_DAT1//////GPIO1_1)
GPIO1_2: P8.5(3) U5.R8(GPMC_AD2/MMC1_DAT2//////GPIO1_2)
GPIO1_3: P8.6(28) U5.T8(GPMC_AD3/MMC1_DAT3//////GPIO1_3)
GPIO1_4: P8.23(12) U5.U8(GPMC_AD4/MMC1_DAT4//////GPIO1_4)
GPIO1_5: P8.22(36) U5.V8(GPMC_AD5/MMC1_DAT5//////GPIO1_5)
GPIO1_6: P8.3(2) U5.R9(GPMC_AD6/MMC1_DAT6//////GPIO1_6)
GPIO1_7: P8.4(27) U5.T9(GPMC_AD7/MMC1_DAT7//////GPIO1_7)
GPIO1_12: P8.12(31) U5.T12(GPMC_AD12/LCD_DATA19/MMC1_DAT4/MMC2_DAT0/EQEP2A_IN/PR1_MII0_TXD2/PR1_PRU0_PRU_R30_14/GPIO1_12)
GPIO1_13: P8.11(6) U5.R12(GPMC_AD13/LCD_DATA18/MMC1_DAT5/MMC2_DAT1/EQEP2B_IN/PR1_MII0_TXD1/PR1_PRU0_PRU_R30_15/GPIO1_13)
GPIO1_14: P8.16(33) U5.V13(GPMC_AD14/LCD_DATA17/MMC1_DAT6/MMC2_DAT2/EQEP2_INDEX/PR1_MII0_TXD0/PR1_PRU0_PRU_R31_14/GPIO1_14)
GPIO1_15: P8.15(8) U5.U13(GPMC_AD15/LCD_DATA16/MMC1_DAT7/MMC2_DAT3/EQEP2_STROBE/PR1_ECAP0_ECAP_CAPIN_APWM_O/PR1_PRU0_PRU_R31_15/GPIO1_15)
GPIO1_16: P9.15(8) U5.R13(GPMC_A0/GMII2_TXEN/RGMII2_TCTL/RMII2_TXEN/GPMC_A16/PR1_MII_MT1_CLK/EHRPWM1_TRIPZONE_INPUT/GPIO1_16)
GPIO1_17: P9.23(12) U5.V14(GPMC_A1/GMII2_RXDV/RGMII2_RCTL/MMC2_DAT0/GPMC_A17/PR1_MII1_TXD3/EHRPWM1_SYNCI_O/GPIO1_17)
GPIO1_28: P9.12(31) U5.U18(GPMC_BE1N/GMII2_COL/GPMC_CSN6/MMC2_DAT3/GPMC_DIR/PR1_MII1_RXLINK/MCASP0_ACLKR/GPIO1_28)
GPIO1_29: P8.26(38) U5.V6(GPMC_CSN0/GPIO1_29)
GPIO1_30: P8.21(11) U5.U9(GPMC_CSN1/GPMC_CLK/MMC1_CLK/PRT1EDIO_DATA_IN6/PRT1_EDIO_DATA_OUT6/PR1_PRU1_PRU_R30_12/PR1_PRU1_PRU_R31_12/GPIO1_30)
GPIO1_31: P8.20(35) U5.V9(GPMC_CSN2/GPMC_BE1N/MMC1_CMD/PR1_EDIO_DATA_IN7/PR1_EDIO_DATA_OUT7/PR1_PRU1_PRU_R30_13/PR1_PRU1_PRU_R31_13/GPIO1_31)
GPIO2_1: P8.18(34) U5.V12(GPMC_CLK/LCD_MEM_CLK/GPMC_WAIT1/MMC2_CLK/PRT1_MII1_TXEN/MCASP0_FSR/GPIO2_1)
GPIO2_6: P8.45(23) R80.2 R100.1 U5.R1(LCD_DATA0/GPMC_A0//EHRPWM2A//PR1_PRU1_PRU_R30_0/PR1_PRU1_PRU_R31_0/GPIO2_6)
GPIO2_7: P8.46(48) R81.2 R101.1 U5.R2(LCD_DATA1/GPMC_A1//EHRPWM2B//PR1_PRU1_PRU_R30_1/PR1_PRU1_PRU_R31_1/GPIO2_7)
GPIO2_8: P8.43(22) R82.2 R102.1 U5.R3(LCD_DATA2/GPMC_A2//EHRPWM2_TRIPZONE_INPUT//PR1_PRU1_PRU_R30_2/PR1_PRU1_PRU_R31_2/GPIO2_8)
GPIO2_9: P8.44(47) R83.2 R103.1 U5.R4(LCD_DATA3/GPMC_A3//EHRPWM2_SYNCI_O//PR1_PRU1_PRU_R30_3/PR1_PRU1_PRU_R31_3/GPIO2_9)
GPIO2_10: P8.41(21) R84.2 R104.1 U5.T1(LCD_DATA4/GPMC_A4//EQEP2A_IN//PR1_PRU1_PRU_R30_4/PR1_PRU1_PRU_R31_4/GPIO2_10)
GPIO2_11: P8.42(46) R85.2 R105.1 U5.T2(LCD_DATA5/GPMC_A5//EQEP2B_IN//PR1_PRU1_PRU_R30_5/PR1_PRU1_PRU_R31_5/GPIO2_11)
GPIO2_12: P8.39(20) R86.2 R106.1 U5.T3(LCD_DATA6/GPMC_A6/PR1_EDIO_DATA_IN6/EQEP2_INDEX/PR1_EDIO_DATA_OUT6/PR1_PRU1_PRU_R30_6/PR1_PRU1_PRU_R31_6/GPIO2_12)
GPIO2_13: P8.40(45) R87.2 R107.1 U5.T4(LCD_DATA7/GPMC_A7/PR1_EDIO_DATA_IN7/EQEP2_STROBE/PR1_EDIO_DATA_OUT7/PR1_PRU1_PRU_R30_7/PR1_PRU1_PRU_R31_7/GPIO2_13)
GPIO2_22: P8.27(14) U5.U5(LCD_VSYNC/GPMC_A8//PR1_EDIO_DATA_IN2/PR1_EDIO_DATA_OUT2/PR1_PRU1_PRU_R30_8/PR1_PRU1_PRU_R31_8/GPIO2_22)
GPIO2_23: P8.29(15) U5.R5(LCD_HSYNC/GPMC_A9//PR1_EDIO_DATA_IN3/PR1_EDIO_DATA_OUT3/PR1_PRU1_PRU_R30_9/PR1_PRU1_PRU_R31_9/GPIO2_23)
GPIO2_24: P8.28(39) U5.V5(LCD_PCLK/GPMC_A10//PR1_EDIO_DATA_IN4/PR1_EDIO_DATA_OUT4/PR1_PRU1_PRU_R30_10/PR1_PRU1_PRU_R31_10/GPIO2_24)
GPIO2_25: P8.30(40) U5.R6(LCD_AC_BIAS_EN/GPMC_A11//PR1_EDIO_DATA_IN5/PR1_EDIO_DATA_OUT5/PR1_PRU1_PRU_R30_11/PR1_PRU1_PRU_R31_11/GPIO2_25)
GPIO3_19: P9.27(14) U5.C13(MCASP0_FSR/EQEP0B_IN/MCASP0_AXR3/MCASP1_FSX/EMU2/PR1_PRU0_PRU_R30_5/PR1_PRU0_PRU_R31_5/GPIO3_19)
GPIO3_21: P9.25(13) U5.A14(MCASP0_AHCLKX/EQEP0_STROBE/MCASP0_AXR3/MCASP1_AXR1/EMU4/PR1_PRU0_PRU_R30_7/PR1_PRU0_PRU_R31_7/GPIO3_21)
GRN_C: P10.10(GRNC) R128.2
GRNA: P10.9(GRNA) U15.3(LED1/REGOFF)
HS_IND: TP8.1(TP) U11.16(HS_IND)
HUB_BIAS: R157.1 U11.26(RBIAS)
I2C0_SCL: R7.2 U2.28(SCL) U5.C16(I2C0_SCL/TIMER7/UART2_RTSN/ECAP1_IN_PWM1_OUT////GPIO3_6) U7.6(SCL)
I2C0_SDA: R4.2 U2.27(SDA) U5.C17(I2C0_SDA/TIMER4/UART2_CTSN/ECAP2_IN_PWM2_OUT////GPIO3_5) U7.5(SDA)
I2C1_SCL: P9.17(9) U5.A16(SPI0_CS0/MMC2_SDWP/I2C1_SCL/EHRPWM0_SYNCI_O/PR1_UART0_TXD/PR1_EDIO_DATA_IN1/PR1_EDIO_DATA_OUT1/GPIO0_5)
I2C1_SDA: P9.18(34) U5.B16(SPI0_D1/MMC1_SDWP/I2C1_SDA/EHRPWM0_TRIPZONE_INPUT/PR1_UART0_RXD/PR1_EDIO_DATA_IN0/PR1_EDIO_DATA_OUT0/GPIO0_4)
I2C2_SCL: P9.19(10) U5.D17(UART1_RTSN/TIMER5/DCAN0_RX/I2C2_SCL/SPI1_CS1/PR1_UART0_RTS_N/PR1_EDC_LATCH1_IN/GPIO0_13)
I2C2_SDA: P9.20(35) U5.D18(UART1_CTSN/TIMER6/DCAN0_TX/I2C2_SDA/SPI1_CS0/PR1_UART0_CTS_N/PR1_EDC_LATCH0_IN/GPIO0_12)
JTAG_EMU0: P7.13(EMU0) R170.2 R176.2 U5.C14(EMU0/GPIO3_7)
JTAG_EMU1: P7.14(EMU1) R171.2 R179.2 U5.B14(EMU1/GPIO3_8)
JTAG_TCK: R164.2 R178.1 R180.1 U5.A12(TCK)
JTAG_TDI: P7.3(TDI) R165.2 U5.B11(TDI)
JTAG_TDO: P7.7(TDO) R166.2 U5.A11(TDO)
JTAG_TMS: P7.1(TMS) R168.2 U5.C11(TMS)
JTAG_TRSTn: P7.2(TRSTn) R169.2 R186.1 U5.B10(NTRST)
LDO3: R19.1 U2.40(LDO3)
LDO4: R121.1 U2.43(LDO4)
LDO_PGOOD: R141.2 U2.46(LDO_PGOOD)
LED2: P10.12(YELA) R219.1 U15.2(LED2/nINTSEL)
LEDAA: D2.2(A) R96.2 TP10.1(TP)
LEDAC: D2.1(C) Q1.6(3)
LEDBA: D3.2(A) R97.2 TP11.1(TP)
LEDBC: D3.1(C) Q1.3
LEDCA: D4.2(A) R98.2 TP12.1(TP)
LEDCC: D4.1(C) Q2.6(3)
LEDDA: D5.2(A) R99.2 TP13.1(TP)
LEDDC: D5.1(C) Q2.3
MDIO_CLK: U5.M18(MDIO_CLK/TIMER5/UART5_TXD/UART3_RTSN/MMC0_SDWP/MMC1_CLK/MMC2_CLK/GPIO0_1) U15.17(MDC)
MDIO_DATA: R131.2 U5.M17(MDIO_DATA/TIMER6/UART5_RXD/UART3_CTSN/MMC0_SDCD/MMC1_CMD/MMC2_CMD/GPIO0_0) U15.16(MDIO)
MMC0_CLKO: P4.5(CLOCK) R192.2 U5.G17(MMC0_CLK/GPMC_A24/UART3_CTSN/UART2_RXD/DCAN1_TX/PR1_PRU0_PRU_R30_12/PR1_PRU0_PRU_R31_12/GPIO2_30)
MMC0_CMD: P4.3(CMD) R191.2 U5.G18(MMC0_CMD/GPMC_A25/UART3_RTSN/UART2_TXD/DCAN1_RX/PR1_PRU0_PRU_R30_13/PR1_PRU0_PRU_R31_13/GPIO2_31)
MMC0_DAT0: P4.7(DAT0) R193.2 U5.G16(MMC0_DAT0/GPMC_A23/UART5_RTSN/UART3_TXD/UART1_RIN/PR1_PRU0_PRU_R30_11/PR1_PRU0_PRU_R31_11/GPIO2_29)
MMC0_DAT1: P4.8(DAT1) R194.2 U5.G15(MMC0_DAT1/GPMC_A22/UART5_CTSN/UART3_RXD/UART1_DTRN/PR1_PRU0_PRU_R30_10/PR1_PRU0_PRU_R31_10/GPIO2_28)
MMC0_DAT2: P4.1(DAT2) R190.2 U5.F18(MMC0_DAT2/GPMC_A21/UART4_RTSN/TIMER6/UART1_DSRN/PR1_PRU0_PRU_R30_9/PR1_PRU0_PRU_R31_9/GPIO2_27)
MMC0_DAT3: P4.2(CD/DAT3) R195.2 U5.F17(MMC0_DAT3/GPMC_A20/UART4_CTSN/TIMER5/UART1_DCDN/PR1_PRU0_PRU_R30_8/PR1_PRU0_PRU_R31_8/GPIO2_26)
nINT/RXCLK/PHYAD1: R215.1 R216.1
NON_REM1: R154.2 R158.1 U11.13(NON_REM1)
NON_REM2: R155.2 R159.1 TP7.1(TP) U11.19(SUSP_IND/NON_REM0)
OSC0_IN: C26.1 R21.1 U5.V10(OSC0_IN) Y2.3 Y3.3
OSC0_OUT: R24.2 U5.U11(OSC0_OUT)
OSC0_OUT1: C27.1 R21.2 R24.1 Y2.1 Y3.1
OSC1_IN: C23.2 U5.A6(OSC1_IN) Y1.1
OSC1_OUT: R22.2 U5.A4(OSC1_OUT)
OSC1_OUT1: C24.2 R22.1 Y1.2
P_BYPASS: C5.2 U2.47(BYPASS)
P_INT_LDO: C4.2 U2.48(INT_LDO)
P_L1: L1.1 U2.20(L1)
P_L2: L2.1 U2.23(L2)
P_L3: L3.1 U2.31(L3)
P_MUXIN: R1.2 R2.1 U2.14(MUX_IN)
P_MUXOUT: R8.2 U2.16(MUX_OUT)
P_WAKEUP: R11.1 U2.13(WAKEUP)
PDDR_A0: R29.2 U5.F3(DDR_A0)
PDDR_A1: R25.2 U5.H1(DDR_A1)
PDDR_A2: R30.2 U5.E4(DDR_A2)
PDDR_A3: R26.2 U5.C3(DDR_A3)
PDDR_A4: R31.2 U5.C2(DDR_A4)
PDDR_A5: R32.2 U5.B1(DDR_A5)
PDDR_A6: R33.2 U5.D5(DDR_A6)
PDDR_A7: R34.2 U5.E2(DDR_A7)
PDDR_A8: R35.2 U5.D4(DDR_A8)
PDDR_A9: R36.2 U5.C1(DDR_A9)
PDDR_A10: R37.2 U5.F4(DDR_A10)
PDDR_A11: R38.2 U5.F2(DDR_A11)
PDDR_A12: R39.2 U5.E3(DDR_A12)
PDDR_A13: R40.2 U5.H3(DDR_A13)
PDDR_BA0: R41.2 U5.C4(DDR_BA0)
PDDR_BA1: R42.2 U5.E1(DDR_BA1)
PDDR_BA2: R43.2 U5.B3(DDR_BA2)
PDDR_CASn: R64.2 U5.F1(DDR_CASN)
PDDR_CKE: R62.2 U5.G3(DDR_CKE)
PDDR_CLK: R60.2 U5.D2(DDR_CK)
PDDR_CLKn: R61.2 U5.D1(DDR_NCK)
PDDR_CSn: R63.2 U5.H2(DDR_CSN0)
PDDR_D0: R44.2 U5.M3(DDR_D0)
PDDR_D1: R45.2 U5.M4(DDR_D1)
PDDR_D2: R46.2 U5.N1(DDR_D2)
PDDR_D3: R47.2 U5.N2(DDR_D3)
PDDR_D4: R48.2 U5.N3(DDR_D4)
PDDR_D5: R49.2 U5.N4(DDR_D5)
PDDR_D6: R50.2 U5.P3(DDR_D6)
PDDR_D7: R51.2 U5.P4(DDR_D7)
PDDR_D8: R52.2 U5.J1(DDR_D8)
PDDR_D9: R53.2 U5.K1(DDR_D9)
PDDR_D10: R54.2 U5.K2(DDR_D10)
PDDR_D11: R55.2 U5.K3(DDR_D11)
PDDR_D12: R56.2 U5.K4(DDR_D12)
PDDR_D13: R57.2 U5.L3(DDR_D13)
PDDR_D14: R58.2 U5.L4(DDR_D14)
PDDR_D15: R59.2 U5.M1(DDR_D15)
PDDR_DQM0: R67.2 U5.M2(DDR_DQM0)
PDDR_DQM1: R70.2 U5.J2(DDR_DQM1)
PDDR_DQS0: R68.2 U5.P1(DDR_DQS0)
PDDR_DQS1: R71.2 U5.L1(DDR_DQS1)
PDDR_DQSN0: R69.2 U5.P2(DDR_DQSN0)
PDDR_DQSN1: R72.2 U5.L2(DDR_DQSN1)
PDDR_ODT: R73.2 U5.G1(DDR_ODT)
PDDR_RASn: R65.2 U5.G4(DDR_RASN)
PDDR_WEn: R66.2 U5.B2(DDR_WEn)
PHY_VDDCR: C124.1 C125.1 U15.6(VDDCR)
PHY_XTAL1: C132.1 R140.2 R199.1 Y4.1
PHY_XTAL2: R140.1 R144.1 U15.4(XTAL2)
PHYX: C131.1 R144.2 Y4.2
PLLFILT: C145.1 U11.25(PLLFILT)
PMIC_INT: R10.2 R28.2 U5.B18(NNMI)
PMIC_INT_PU: R28.1 U14.7(2Y)
PMIC_INT_SRC: R10.1 R203.2 U2.45(INT) U14.1(2A) U14.2(2B)
PMIC_PGOOD: C25.1 R20.1 U2.26(PGOOD) U5.B15(PORZ)
PMIC_POWR_EN: U2.9(PWR_EN) U5.C6(PMIC_POWER_EN)
PWR_BUT: P9.9(5) U2.25(PB_IN)
PWR_LED: R6.1 U2.1(VLDO2)
PWR_LEDR: D1.2(A) R6.2 TP14.1(TP)
RBIAS: R145.1 U15.32(RBIAS)
RCLKIN: R199.2 R200.2 U15.5(XTAL1/CLKIN)
REFCLKO: R136.2 R209.2 U15.7(RXCLK/PHYAD1)
RESETn: C136.1 R156.2 U11.17(~{RESET})
RMII1_COL: R207.1 U5.H16(GMII1_COL/RMII2_REFCLK/SPI1_SCLK/UART5_RXD/MCASP1_AXR2/MMC2_DAT3/MCASP0_AXR2/GPIO3_0)
RMII1_CRS_DV: R139.1 U5.H17(GMII1_CRS/RMII1_CRS_DV/SPI1_D0/I2C1_SDA/MCASP1_ACLKX/UART5_CTSN/UART2_RXD/GPIO3_1)
RMII1_REFCLK: R200.1 R201.2 R209.1
RMII1_RXCLK: R136.1 U5.L18(GMII1_RXCLK/UART2_TXD/RGMII1_RCLK/MMC0_DAT6/MMC1_DAT1/UART1_DSRN/MCASP0_FSX/GPIO3_10)
RMII1_RXD0: R135.1 U5.M16(GMII1_RXD0/RMII1_RXD0/RGMII1_RD0/MCASP1_AHCLKX/MCASP1_AHCLKR/MCASP1_ACLKR/MCASP0_AXR3/GPIO2_21)
RMII1_RXD1: R132.1 U5.L15(GMII1_RXD1/RMII1_RXD1/RGMII1_RD1/MCASP1_AXR3/MCASP1_FSR/EQEP0_STROBE/MMC2_CLK/GPIO2_20)
RMII1_RXD2: R153.1 U5.L16(GMII1_RXD2/UART3_TXD/RGMII1_RD2/MMC0_DAT4/MMC1_DAT3/UART1_RIN/MCASP0_AXR1/GPIO2_19)
RMII1_RXD3: R205.1 U5.L17(GMII1_RXD3/UART3_RXD/RGMII1_RD3/MMC0_DAT5/MMC1_DAT2/UART1_DTRN/MCASP0_AXR0/GPIO2_18)
RMII1_RXDV: R208.1 U5.J17(GMII1_RXDV/LCD_MEMORY_CLK/RGMII1_RCTL/UART5_TXD/MCASP1_ACLKX/MMC2_DAT0/MCASP0_ACLKR/GPIO3_4)
RMII1_RXERR: R137.1 U5.J15(GMII1_RXERR/RMII1_RXERR/SPI1_D1/I2C1_SCL/MCASP1_FSX/UART5_RTSN/UART2_TXD/GPIO3_2)
RMII1_TXCLK: R206.1 U5.K18(GMII1_TXCLK/UART2_RXD/RGMII1_TCLK/MMC0_DAT7/MMC1_DAT0/UART1_DCDN/MCASP0_ACLKX/GPIO3_9)
RMII1_TXD0: U5.K17(GMII1_TXD0/RMII1_TXD0/RGMII1_TD0/MCASP1_AXR2/MCASP1_ACLKR/EQEP0B_IN/MMC1_CLK/GPIO0_28) U15.22(TXD0)
RMII1_TXD1: U5.K16(GMII1_TXD1/RMII1_TXD1/RGMII1_TD1/MCASP1_FSR/MCASP1_AXR1/EQEP0A_IN/MMC1_CMD/GPIO0_21) U15.23(TXD1)
RMII1_TXD2: U5.K15(GMII1_TXD2/DCAN0_RX/RGMII1_TD2/UART4_TXD/MCASP1_AXR0/MMC2_DAT2/MCASP0_AHCLKX/GPIO0_17) U15.24(TXD2)
RMII1_TXD3: U5.J18(GMII1_TXD3/DCAN0_TX/RGMII1_TD3/UART4_RXD/MCASP1_FSX/MMC2_DAT1/MCASP0_FSR/GPIO0_16) U15.25(TXD3)
RMII1_TXEN: U5.J16(GMII1_TXEN/RMII1_TXEN/RGMII1_TCTL/TIMER4/MCASP1_AXR0/EQEP0_INDEX/MMC2_CMD/GPIO3_3) U15.21(TXEN)
rsvd3: R161.2 U11.15(VSS)
RTC_PORZ: R18.1 R141.1 R143.2 U5.B5(RTC_PORZ)
RTCK: P7.9(TCKRTN) R178.2
RXD0/MODE0: R124.1 R135.2 R198.1 U15.11(RXD0/MODE0)
RXD1/MODE1: R5.1 R123.1 R132.2 U15.10(RXD1/MODE1)
RXD2/RMIISEL: R153.2 R211.1 R212.1 U15.9(RXD2/RMIISEL)
RXD3/PHYAD2: R205.2 R213.1 R214.1 U15.8(RXD3/PHYAD2)
RXDV: R208.2 U15.26(RXDV)
RXER/PHYAD0: R125.1 R126.2 R137.2 U15.13(RXER/RXD4/PHYAD0)
RXN: C127.1 P10.2(RD-) R130.1 U15.30(RXN)
RXP: C126.1 P10.1(RD+) R129.1 U15.31(RXP)
SD_CD: P4.11(GND1) R196.1 R197.1
SPI1_CS0: P9.28(39) U5.C12(MCASP0_AHCLKR/EHRPWM0_SYNCI_O/MCASP0_AXR2/SPI1_CS0/ECAP2_IN_PWM2_OUT/PR1_PRU0_PRU_R30_3/PR1_PRU0_PRU_R31_3/GPIO3_17)
SPI1_D0: P9.29(15) U5.B13(MCASP0_FSX/EHRPWM0B//SPI1_D0/MMC1_SDCD/PR1_PRU0_PRU_R30_1/PR1_PRU0_PRU_R31_1/GPIO3_15)
SPI1_D1: P9.30(40) U5.D12(MCASP0_AXR0/EHRPWM0_TRIPZONE_INPUT//SPI1_D1/MMC2_SDCD/PR1_PRU0_PRU_R30_2/PR1_PRU0_PRU_R31_2/GPIO3_16)
SPI1_SCLK: P9.31(16) U5.A13(MCASP0_ACLKX/EHRPWM0A//SPI1_SCLK/MMC0_SDCD/PR1_PRU0_PRU_R30_0/PR1_PRU0_PRU_R31_0/GPIO3_14)
SYS_5V: C133.1 FB4.2 P9.7(4) P9.8(29) R3.2 R152.1 U2.7(SYS1) U2.8(SYS2) U9.2(IN) U9.3(IN)
SYS_RESETn: P9.10(30) R23.2 R27.1 U5.A10(NRESET_INOUT) U15.19(nRST)
SYS_VOLT: C6.1 C8.2 C9.2 C10.2 C17.2 C18.2 C19.2 R2.2 R3.1 U2.2(VINLDO) U2.21(VIN_DCDC1) U2.22(VIN_DCDC2) U2.32(VIN_DCDC3) U2.39(LDO3_IN) U2.42(LDO4_IN) U8.8(IN)
SYS_WARMRESETn: C101.1 R27.2 R163.2 S1.2(A2)
TCK: P7.11(TCK) R180.2
TCT_RCT: C130.1 P10.4(RCT) P10.5(TCT) R142.1
TDIS: P7.4(TDIS) R177.1
TESTOUT: TP6.1(TP) U5.A3(TESTOUT)
TIMER4: P8.7(4) U5.R7(GPMC_ADVN_ALE/TIMER4/GPIO2_2)
TIMER5: P8.9(5) U5.T6(GPMC_BE0N_CLE/TIMER5/GPIO2_5)
TIMER6: P8.10(30) U5.U6(GPMC_WEN/TIMER6/GPIO2_4)
TIMER7: P8.8(29) U5.T7(GPMC_OEN_REN/TIMER7/EMU4/GPIO2_3)
TXCLK: R206.2 U15.20(TXCLK)
TXN: C129.1 P10.6(TD-) R134.1 U15.28(TXN)
TXP: C128.1 P10.3(TD+) R133.1 U15.29(TXP)
U5_H18: R201.1 U5.H18(RMII1_REFCLK/XDMA_EVENT_INTR2/SPI1_CS0/UART5_TXD/MCASP1_AXR3/MMC0_POW/MCASP1_AHCLKX/GPIO0_29)
UART0_CTS: U5.E17(UART0_RTSN/UART4_TXD/DCAN1_RX/I2C1_SCL/SPI1_D1/SPI1_CS0/PR1_EDC_SYNC1_OUT/GPIO1_9) U12.40(BDBUS2)
UART0_RTS: U5.E18(UART0_CTSN/UART4_RXD/DCAN1_TX/I2C1_SDA/SPI1_D0/TIMER7/PR1_EDC_SYNC0_OUT/GPIO1_8) U12.41(BDBUS3)
UART0_RX: U5.E16(UART0_TXD/SPI1_CS1/DCAN0_RX/I2C2_SCL/ECAP1_IN_PWM1_OUT/PR1_PRU1_PRU_R30_15/PR1_PRU1_PRU_R31_15/GPIO1_11) U12.39(BDBUS1)
UART0_TX: U5.E15(UART0_RXD/SPI1_CS0/DCAN0_TX/I2C2_SDA/ECAP2_IN_PWM2_OUT/PR1_PRU1_PRU_R30_14/PR1_PRU1_PRU_R31_14/GPIO1_10) U12.38(BDBUS0)
UART1_RXD: P9.26(38) U5.D16(UART1_RXD/MMC1_SDWP/DCAN1_TX/I2C1_SDA//PR1_UART0_RXD/PR1_PRU1_PRU_R31_16/GPIO0_14)
UART1_TXD: P9.24(37) U5.D15(UART1_TXD/MMC2_SDWP/DCAN1_RX/I2C1_SCL//PR1_UART0_TXD/PR1_PRU0_PRU_R31_16/GPIO0_15)
UART2_RXD: P9.22(36) U5.A17(SPI0_SCLK/UART2_RXD/I2C2_SDA/EHRPWM0A/PR1_UART0_CTS_N/PR1_EDIO_SOF/EMU2/GPIO0_2)
UART2_TXD: P9.21(11) U5.B17(SPI0_D0/UART2_TXD/I2C2_SCL/EHRPWM0B/PR1_UART0_RTS_N/PR1_EDIO_LATCH_IN/EMU3/GPIO0_3)
UART3_CTSN: P8.36(43) R90.2 R110.1 U5.U3(LCD_DATA10/GPMC_A14/EHRPWM1A/MCASP0_AXR0//PR1_MII0_RXD1/UART3_CTSN/GPIO2_16)
UART3_RTSN: P8.34(42) R91.2 R111.1 U5.U4(LCD_DATA11/GPMC_A15/EHRPWM1B/MCASP0_AHCLKR/MCASP0_AXR2/PR1_MII0_RXD0/UART3_RTSN/GPIO2_17)
UART4_CTSN: P8.35(18) R92.2 R112.1 U5.V2(LCD_DATA12/GPMC_A16/EQEP1A_IN/MCASP0_ACLKR/MCASP0_AXR2/PR1_MII0_RXLINK/UART4_CTSN/GPIO0_8)
UART4_RTSN: P8.33(17) R93.2 R113.1 U5.V3(LCD_DATA13/GPMC_A17/EQEP1B_IN/MCASP0_FSR/MCASP0_AXR3/PR1_MII0_RXER/UART4_RTSN/GPIO0_9)
UART4_RXD: P9.11(6) U5.T17(GPMC_WAIT0/GM112_CRS/GPMC_CSN4/RMII2_CRS_DV/MMC1_SDCD/PR1_MII1_RXDV/UART4_RXD/GPIO0_30)
UART4_TXD: P9.13(7) U5.U17(GPMC_WPN/GMII2_RXERR/GPMC_CSN5/RMII2_RXERR/MMC2_SDCD/PR1_MDIO_MDCLK/UART4_TXD/GPIO0_31)
UART5_CTSN: P8.31(16) R94.2 R114.1 U5.V4(LCD_DATA14/GPMC_A18/EQEP1_INDEX/MCASP0_AXR1/UART5_RXD/PR1_MII_MR0_CLK/UART5_CTSN/GPIO0_10)
UART5_RTSN: P8.32(41) R95.2 R115.1 U5.T5(LCD_DATA15/GPMC_A19/EQEP1_STROBE/MCASP0_AHCLKX/MCASP0_AXR3/PR1_MII0_RXDV/UART5_RTSN/GPIO0_11)
UART5_RXD: P8.38(44) R89.2 R109.1 U5.U2(LCD_DATA9/GPMC_A13/EHRPWM1_SYNCI_O/MCASP0_FSX/UART5_RXD/PR1_MII0_RXD2/UART2_RTSN/GPIO2_15)
UART5_TXD: P8.37(19) R88.2 R108.1 U5.U1(LCD_DATA8/GPMC_A12/EHRPWM1_TRIPZONE_INPUT/MCASP0_ACLKX/UART5_TXD/PR1_MII0_RXD3/UART2_CTSN/GPIO2_14)
USB0_DM: U5.N18(USB0_DM) U11.2(USBDM_DN2)
USB0_DP: U5.N17(USB0_DP) U11.3(USBDP_DN2)
USB0_ID: TP4.1(TP) U5.P16(USB0_ID)
USB0_VBUS: R152.2 U5.P15(USB0_VBUS) U16.4(2Y)
USB0_VBUS_PWR: U11.11(PRTPWR2) U16.3(2A)
USB1_DM: P2.2(P2) U5.R18(USB1_DM) U10.2(D-)
USB1_DP: P2.3(P3) U5.R17(USB1_DP) U10.1(D+)
USB1_DRVVBUS: R147.1 U5.F15(USB1_DRVVBUS/GPIO3_13) U9.4(EN)
USB1_ID: R146.1 U5.P17(USB1_ID)
USB1_OC: R148.2 U5.T16(GPMC_A10/GMII2_RXD1/RGMII2_RD1/RMII2_RXD1/GPMC_A26/PR1_MII1_CRS/MCASP0_AXR0/GPIO1_26) U9.5(~{OC})
USB1_VBUS: C134.1 P2.1(P1) U5.T18(USB1_VBUS) U9.6(OUT) U9.7(OUT) U9.8(OUT) U10.6(VBUS)
USB_DC: C2.1 P3.1(VB) R149.1 U2.12(USB)
USBDM_DN: P3.2(D-) U11.21(USBDM_UP)
USBDP_UP: P3.3(D+) U11.22(USBDP_UP)
USR0: Q1.2(5) R116.1 U5.V15(GPMC_A5/GMII2_TXD0/RGMII2_TD0/RMII2_TXD0/GPMC_A21/PR1_MII1_RXD3/EQEP1B_IN/GPIO1_21)
USR1: Q1.5 R117.1 U5.U15(GPMC_A6/GMII2_TXCLK/RGMII2_TCLK/MMC2_DAT4/GPMC_A22/PR1_MII1_RXD2/EQEP1_INDEX/GPIO1_22)
USR2: Q2.2(5) R118.1 U5.T15(GPMC_A7/GMII2_RXCLK/RGMII2_RCLK/MMC2_DAT5/GPMC_A23/PR1_MII1_RXD1/EQEP1_STROBE/GPIO1_23)
USR3: Q2.5 R119.1 U5.V16(GPMC_A8/GMII2_RXD3/RGMII2_RD3/MMC2_DAT6/GPMC_A24/PR1_MII1_RXD0/MCASP0_ACLKX/GPIO1_24)
VDCDC1: L1.2 R12.1 U2.19(VDCDC1)
VDCDC2: L2.2 R204.1 U2.24(VDCDC2)
VDCDC3: L3.2 R13.1 U2.29(VDCDC3)
VREFP_ADC: C28.1 C29.1 C30.1 R78.2 U5.B9(VREFP)
VRTC: C20.1 C21.1 C98.1 R77.1 U2.3(VLDO1) U5.D7(VDDS_RTC) U17.1(2A) U17.2(2B) U17.8(VCC)
VRTC_DET: R17.1 U17.7(2Y)
VRTC_DET_OUT: R143.1 U17.3(2Y)
VRTC_DETB: C22.1 R17.2 U17.5(2A) U17.6(2B)
WAKEUP: R11.2 R77.2 U5.C5(EXT_WAKEUP)
WP: R210.2 U7.7(WP)
XDMA_EVENT_INTR0: R183.1 U5.A15(EVENT_INTR0/TIMER4/CLKOUT1/SPI1_CS1/PR1PRU1R31_16/EMU2/GPIO0_19)
XTALIN: C137.2 R160.1 U11.24(XTALIN/CLKIN) Y5.3
XTALOUT: C144.2 R160.2 U11.23(XTALOUT) Y5.1
XTIN: C153.2 U12.2(OSCIN) Y6.3(X3)
XTOUT: C155.2 U12.3(OSC0) Y6.1(X1)
YEL_C: P10.11(YELC) R16.2

Not connected (* = marked no-connect by the designer): P3 4(ID)*; P5 3; P7 6(NC); P10 7(NC)*; U1 3(~{FLAG})*; U2 15(NC)* 17(NC1)* 44(RESET)*; U5 B12(MCASP0_ACLKR/EQEP0A_IN/MCASP0_AXR2/MCASP1_ACLKX/MMC0_SDWP/PR1_PRU0_PRU_R30_4/PR1_PRU0_PRU_R31_4/GPIO3_18)* D3(DDR_A15)* D13(MCASP0_AXR1/EQEP0_INDEX//MCASP1_AXR0/EMU3/PR1_PRU0_PRU_R30_6/PR1_PRU0_PRU_R31_6/GPIO3_20)* F16(USB0_DRVVBUS/GPIO0_18) H4(DDR_A14) M15(USB0_CE)* P18(USB1_CE)* R14(GPMC_A4/GMII2_TXD1/RGMII2_TD1/RMII2_TXD1/GPMC_A20/PR1_MII1_TXD0/EQEP1A_IN/GPIO1_20)* T13(GPMC_CSN3/MMC2_CMD/PR1_MDIO_DATA/GPIO2_0)* U16(GPMC_A9/GMII2_RXD2/RGMII2_RD2/MMC2_DAT7/GPMC_A25/PR1_MII_MR1_CLK/MCASP0_FSX/GPIO1_25)* V17(GPMC_A11/GMII2_RXD0/RGMII2_RD0/RMII2_RXD0/GPMC_A27/PR1_MII1_RXER/MCASP0_AXR1/GPIO1_27)*; U6 A2(NC2)* E2(NC1)* R3(RFU1)* R7(RFU2)*; U8 2(NC1)* 6(NC2)* 7(NC3)*; U10 3(ID)* 5(NC)*; U11 5(NC)* 8(~{OCS1})* 12(~{OCS2})*; U12 22(ADBUS5)* 24(ADBUS7)* 27(ACBUS1)* 29(ACBUS3)* 33(ACBUS6)* 34(ACBUS7)* 36(~{SUSPEND})* 43(BDBUS4)* 44(BDBUS5)* 45(BDBUS6)* 46(BDBUS7)* 48(BCBUS0)* 52(BCBUS1)* 53(BCBUS2)* 54(BCBUS3)* 55(BCBUS4)* 57(BCBUS5)* 58(BCBUS6)* 60(~{PWREN})*; U15 18(nINT/TXER/TXD4)*; Y2 2(NC0)* 4(NC1)*; Y3 2(NC0)* 4(NC1)*; Y5 2(NC0)* 4(NC1)*; Y6 2(X2)* 4(X4)*

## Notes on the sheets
sheet 1
- REV
- Description
- DATE
- BY
- A3
- Production release.
- 10/21/2011
- GC
- PAGE NO.
- SCHEMATIC PAGE
- Updated in conjunction with the release of the SRM. Typos and naming changes. No change
  in design.
- A3A
- 11/5/2011
- GC
- 1. Changed supplier for the SD card connector due to availability issue. Created a dual footprint
  for two differrent parts. SD connector is now reversed, so label down is the new orientation.
- 1
- COVER PAGE
- 2
- POWER MANAGEMENT
- 2. Changed R76 from a 50 ohm to 49.9 ohm. Smaller package and lower cost. Changed
  footprint to 0402.
- A4
- 3. Changed C99 termination to DGND.
- 12/1/2011
- GC
- 3
- PROCESSOR 1 OF 3
- 4. Added 10K pulldown to fix link speed LED.
- 4
- PROCESSOR 2 OF 3
- 5. Changed C7 to a 0805 package in PCB layout.
- 1. Changed R219 to DNI. It was causing issues with Ethernet DHCP IP address aquisition. Will
  be added back in on revision A6.
  2. Removed VDD_CORE rail from VPP PIN. Ball on procesor was removed before assembly.
  PCB will be changed in Revision A6.
- 5
- PROCESSOR 3 OF 3
- 2/3/2012
- GC
- 6
- LED, CONFIGURATION AND BUTTON
- A5
- 7
- MEMORY
- 8
- ETHERNET AND USB HOST
- 9
- USB CONCENTRATOR
- This schematic is  *NOT SUPPORTED* and DOES NOT constitute
  a reference design. Only “community” support is allowed
  via resources at BeagleBoard.org/discuss.
  THERE IS NO WARRANTY FOR THIS DESIGN , TO THE EXTENT
  PERMITTED BY APPLICABLE LAW. EXCEPT WHEN OTHERWISE STATED
  IN WRITING THE COPYRIGHT HOLDERS AND/OR OTHER PARTIES
  PROVIDE THE DESIGN “AS IS” WITHOUT WARRANTY OF ANY KIND,
  EITHER EXPRESSED OR IMPLIED, INCLUDING, BUT NOT LIMITED
  TO, THE IMPLIED WARRANTIES OF MERCHANTABILITY AND FITNESS
  FOR A PARTICULAR PURPOSE. THE ENTIRE RISK AS TO THE
  QUALITY AND PERFORMANCE OF THE DESIGN IS WITH YOU. SHOULD
  THE DESIGN PROVE DEFECTIVE, YOU ASSUME THE COST OF ALL
  NECESSARY SERVICING, REPAIR OR CORRECTION.
- 10
- SERIAL AND JTAG
- 11
- EXP CONN, uSD, AND LDO
- NOTE: PCB Revision for this board is Rev C1.
sheet 2
- 5V DC POWER
- EXPANSION HEADER
- 3.25V
- 1.8V@100mA
- POWER LED
sheet 5
- CONNECTION HAS BEEN REMOVED.
sheet 6
- SYS_BOOT0
- SYS_BOOT1
- SYS_BOOT2
- SYS_BOOT3
- SYS_BOOT4
- SYS_BOOT5
- USR0
- USR1
- SYS_BOOT6
- SYS_BOOT7
- USR2
- USR3
- SYS_BOOT8
- SYS_BOOT9
- SYS_BOOT10
- SYS_BOOT11
- SYS_BOOT12
- SYS_BOOT13
- SYS_BOOT14
- SYS_BOOT15
- Boot Configuration
- User LED's
- BOOT ORDER....MMC....SPI....UART....USB......24MHZ
- RESET BUTTON
sheet 7
- Variable  & MAC Memory
- 256KX8
- DDR2 SDRAM
sheet 8
- NOTE: There are two different configuration
  connectors used for P10. The difference is
  that the TX and RX pairs are swapped.
  Either of these can be used as the
  AUTO_MDIX feature in the LAN8710A will
  compensate by swapping the TX and Rx on
  the LAN8710.
- ETHERNET
  CONNECTOR
- NOT INSTALLED
- ESD_RING
- ACTIVE WHEN LINK PRESENT.
  BLINKS OFF DURING ACTIVITY.
- ACTIVE WHEN AT 100MB
- PHYAD0
- MODE2
- MODE1
- MODE0
- RMISEL
- PHYAD1
- PHYAD0
- USB HOST CONNECTOR
sheet 9
- USB PC
  CONNECTOR
sheet 10
- OPTIONAL JTAG
sheet 11
- EXPANSION HEADER
- EXPANSION HEADER
- uSD CONNECTOR
